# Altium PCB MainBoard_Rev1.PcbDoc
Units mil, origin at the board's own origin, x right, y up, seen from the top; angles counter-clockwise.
Board outline 3937.5 x 3937.01 mil, 4 copper layers (Layer 1, Layer 2, Layer 3, Layer 4), stack 68.734 mil thick; 72 components, 52 nets, 360 pads, 166 vias.
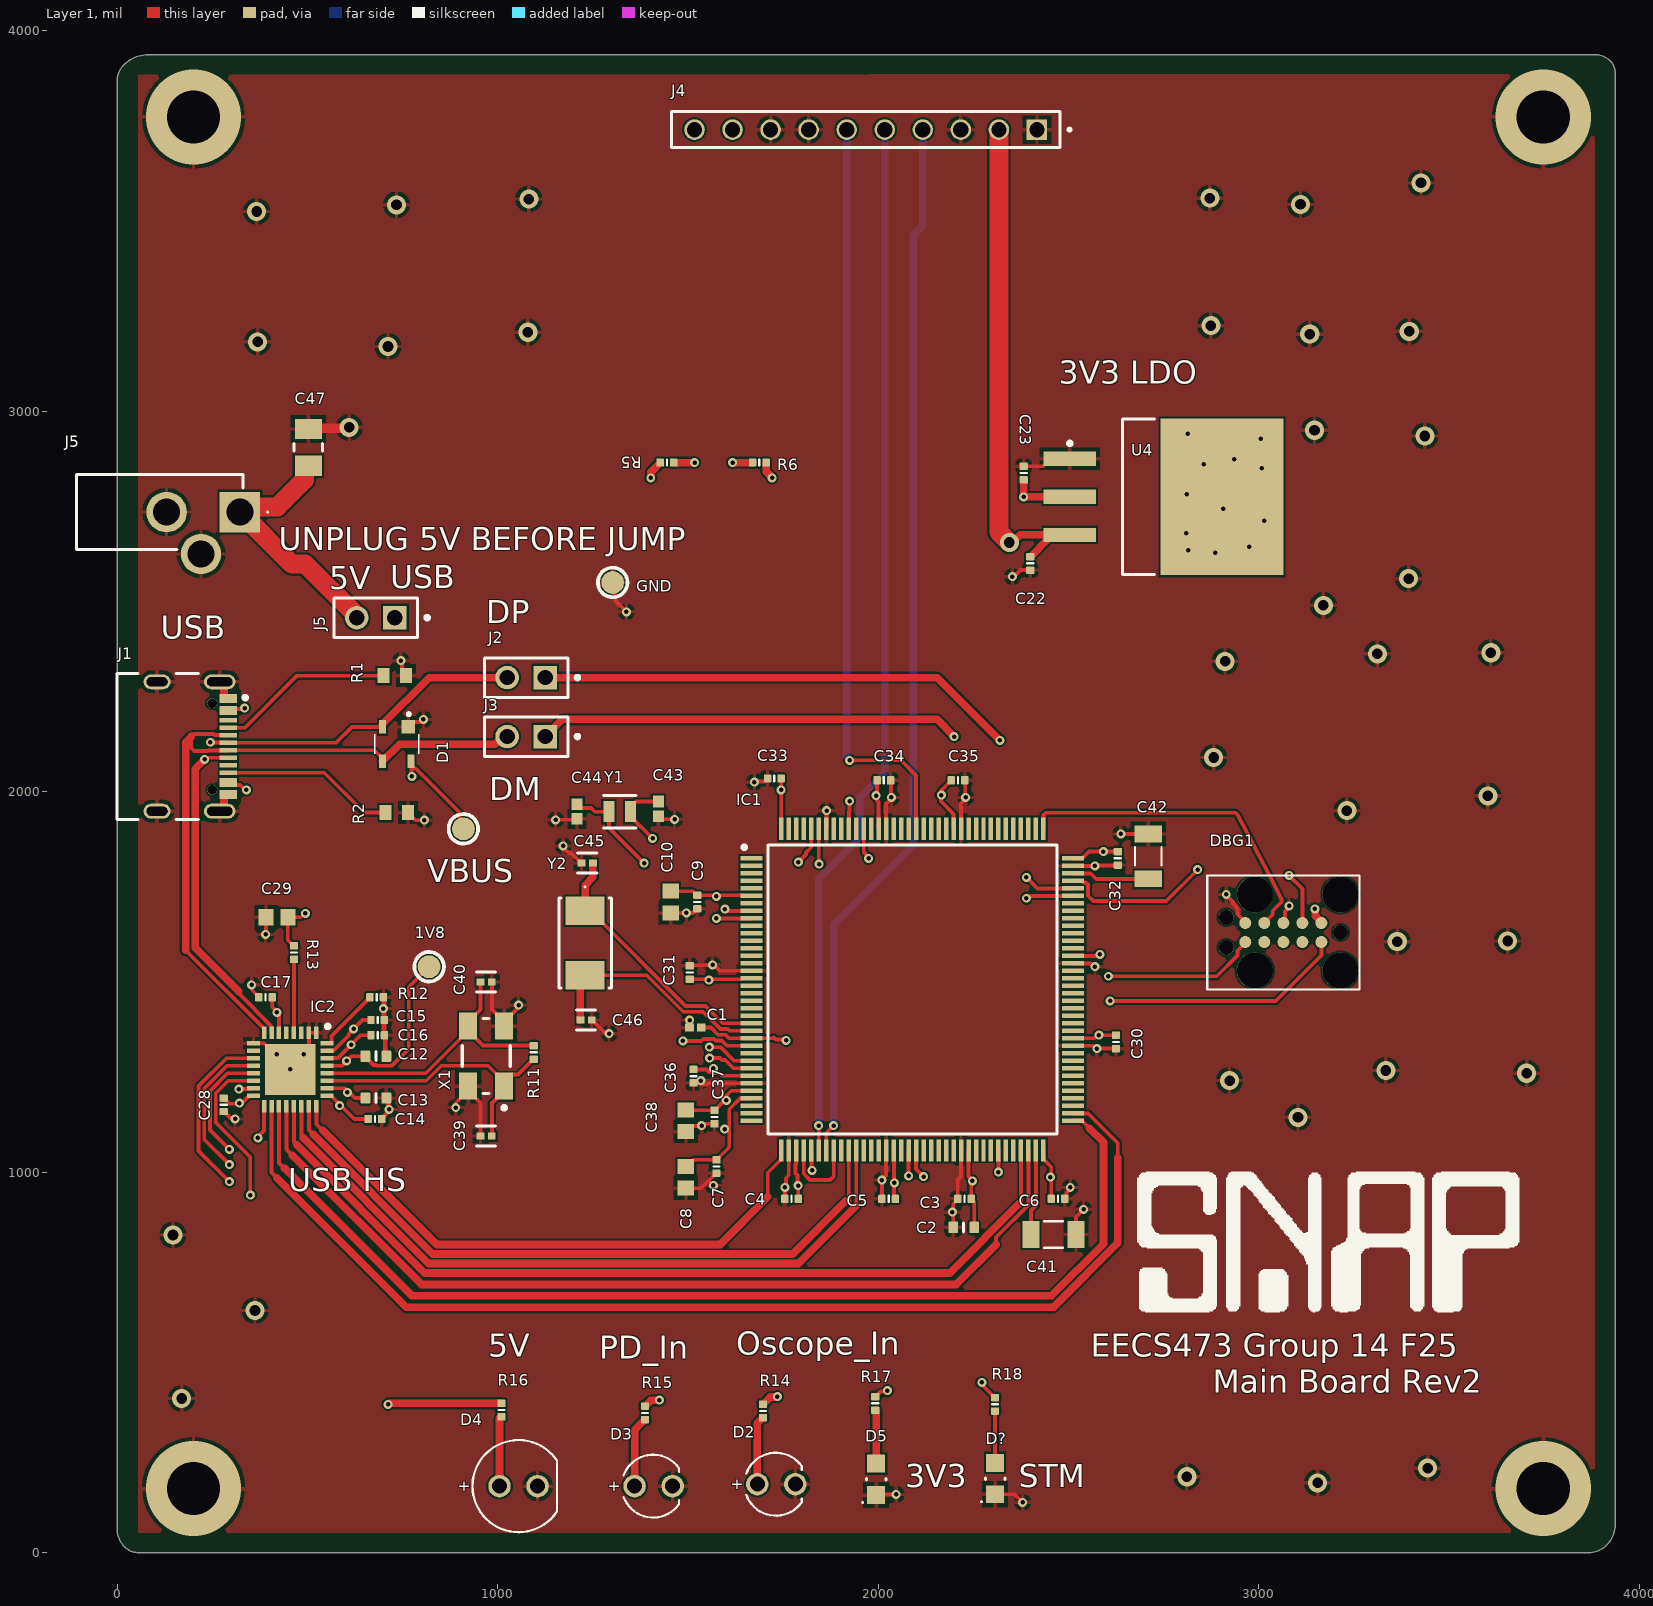
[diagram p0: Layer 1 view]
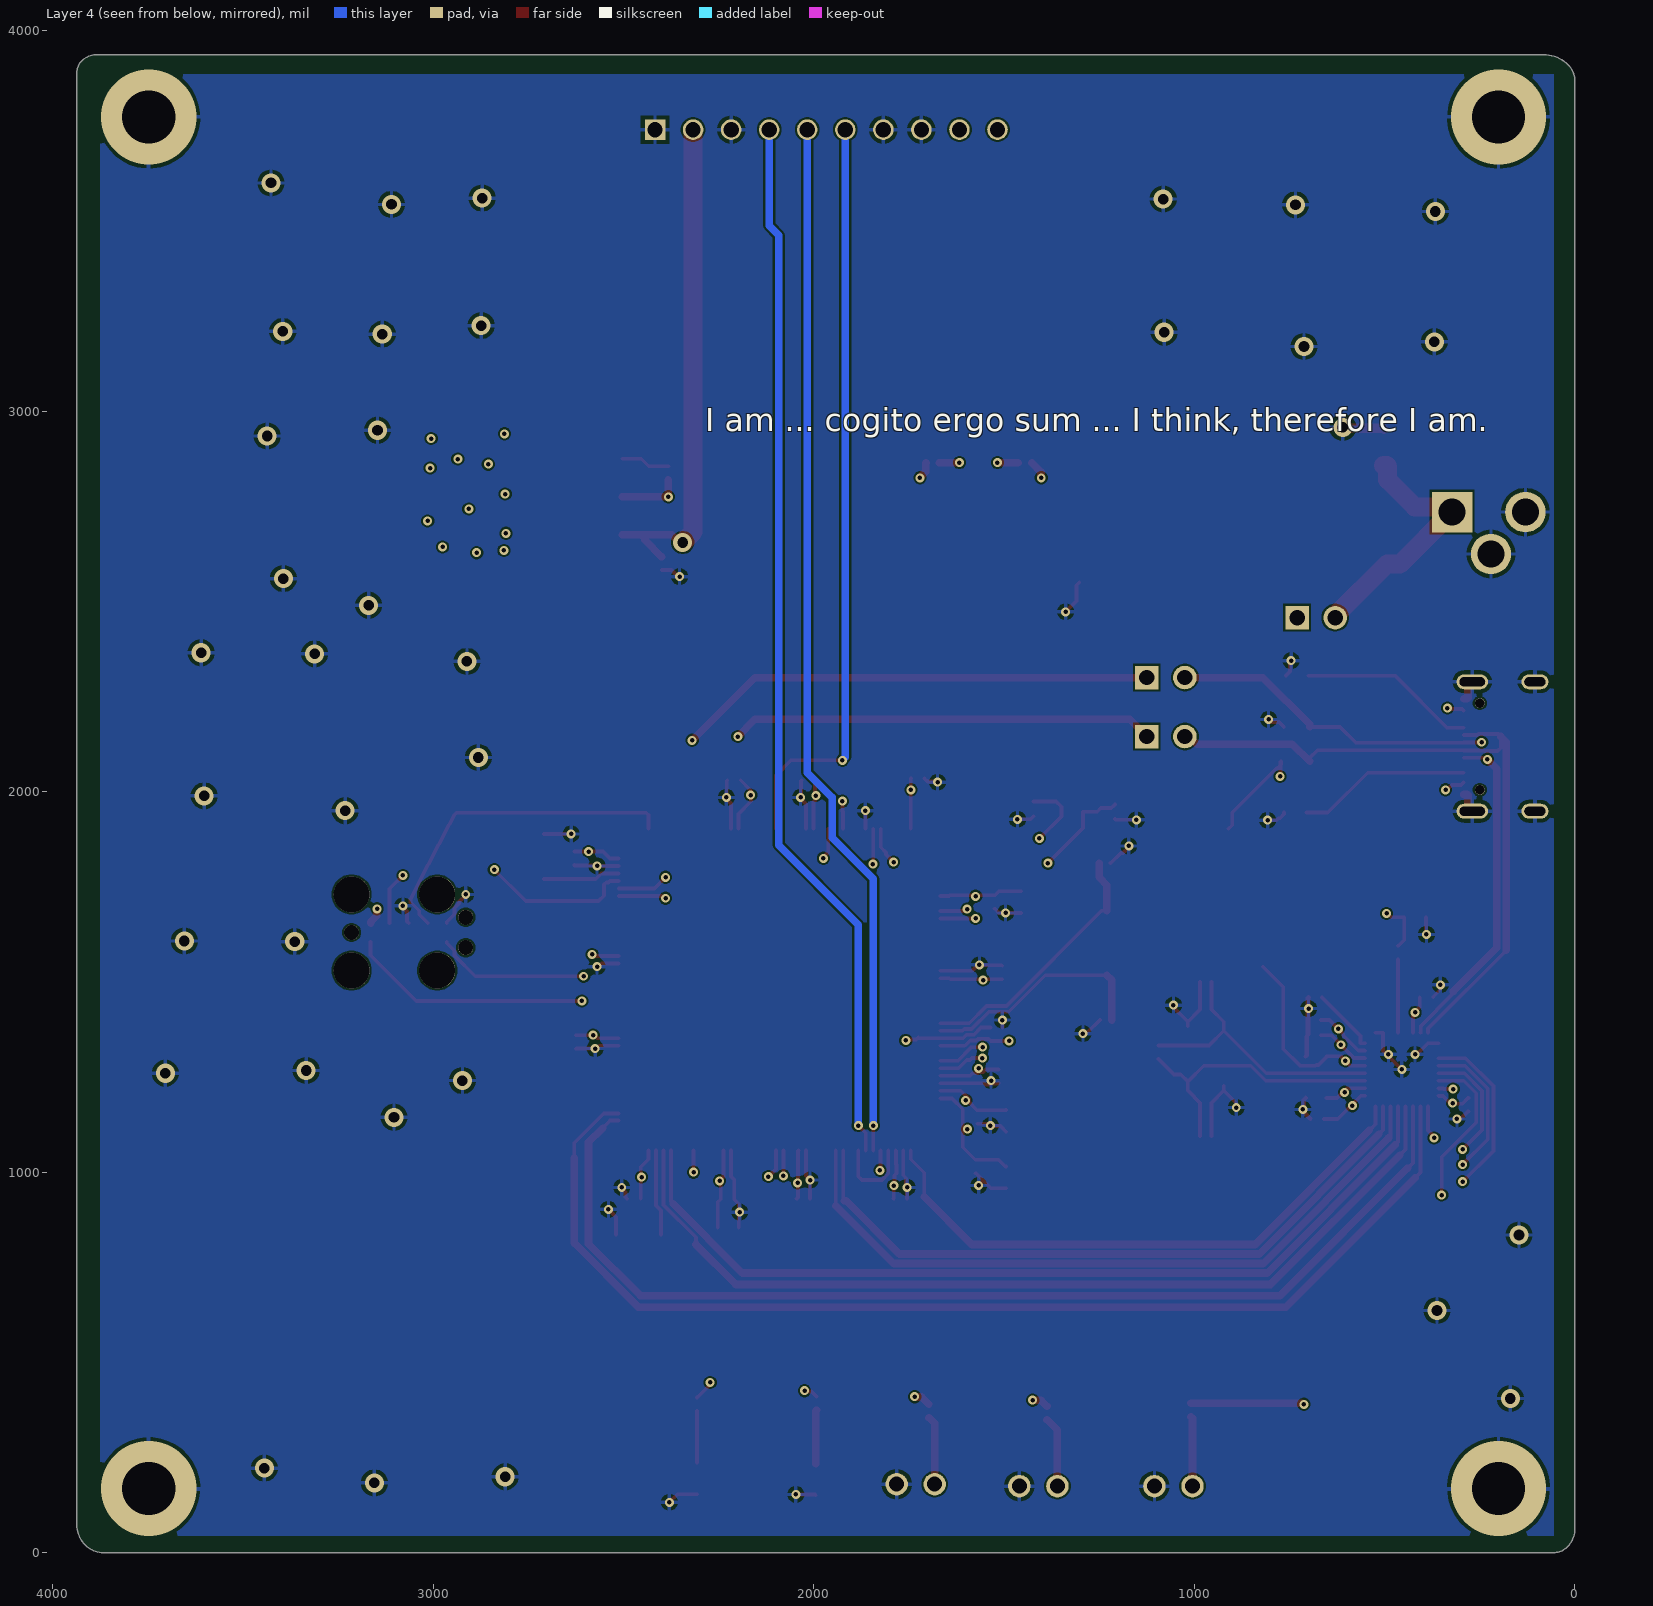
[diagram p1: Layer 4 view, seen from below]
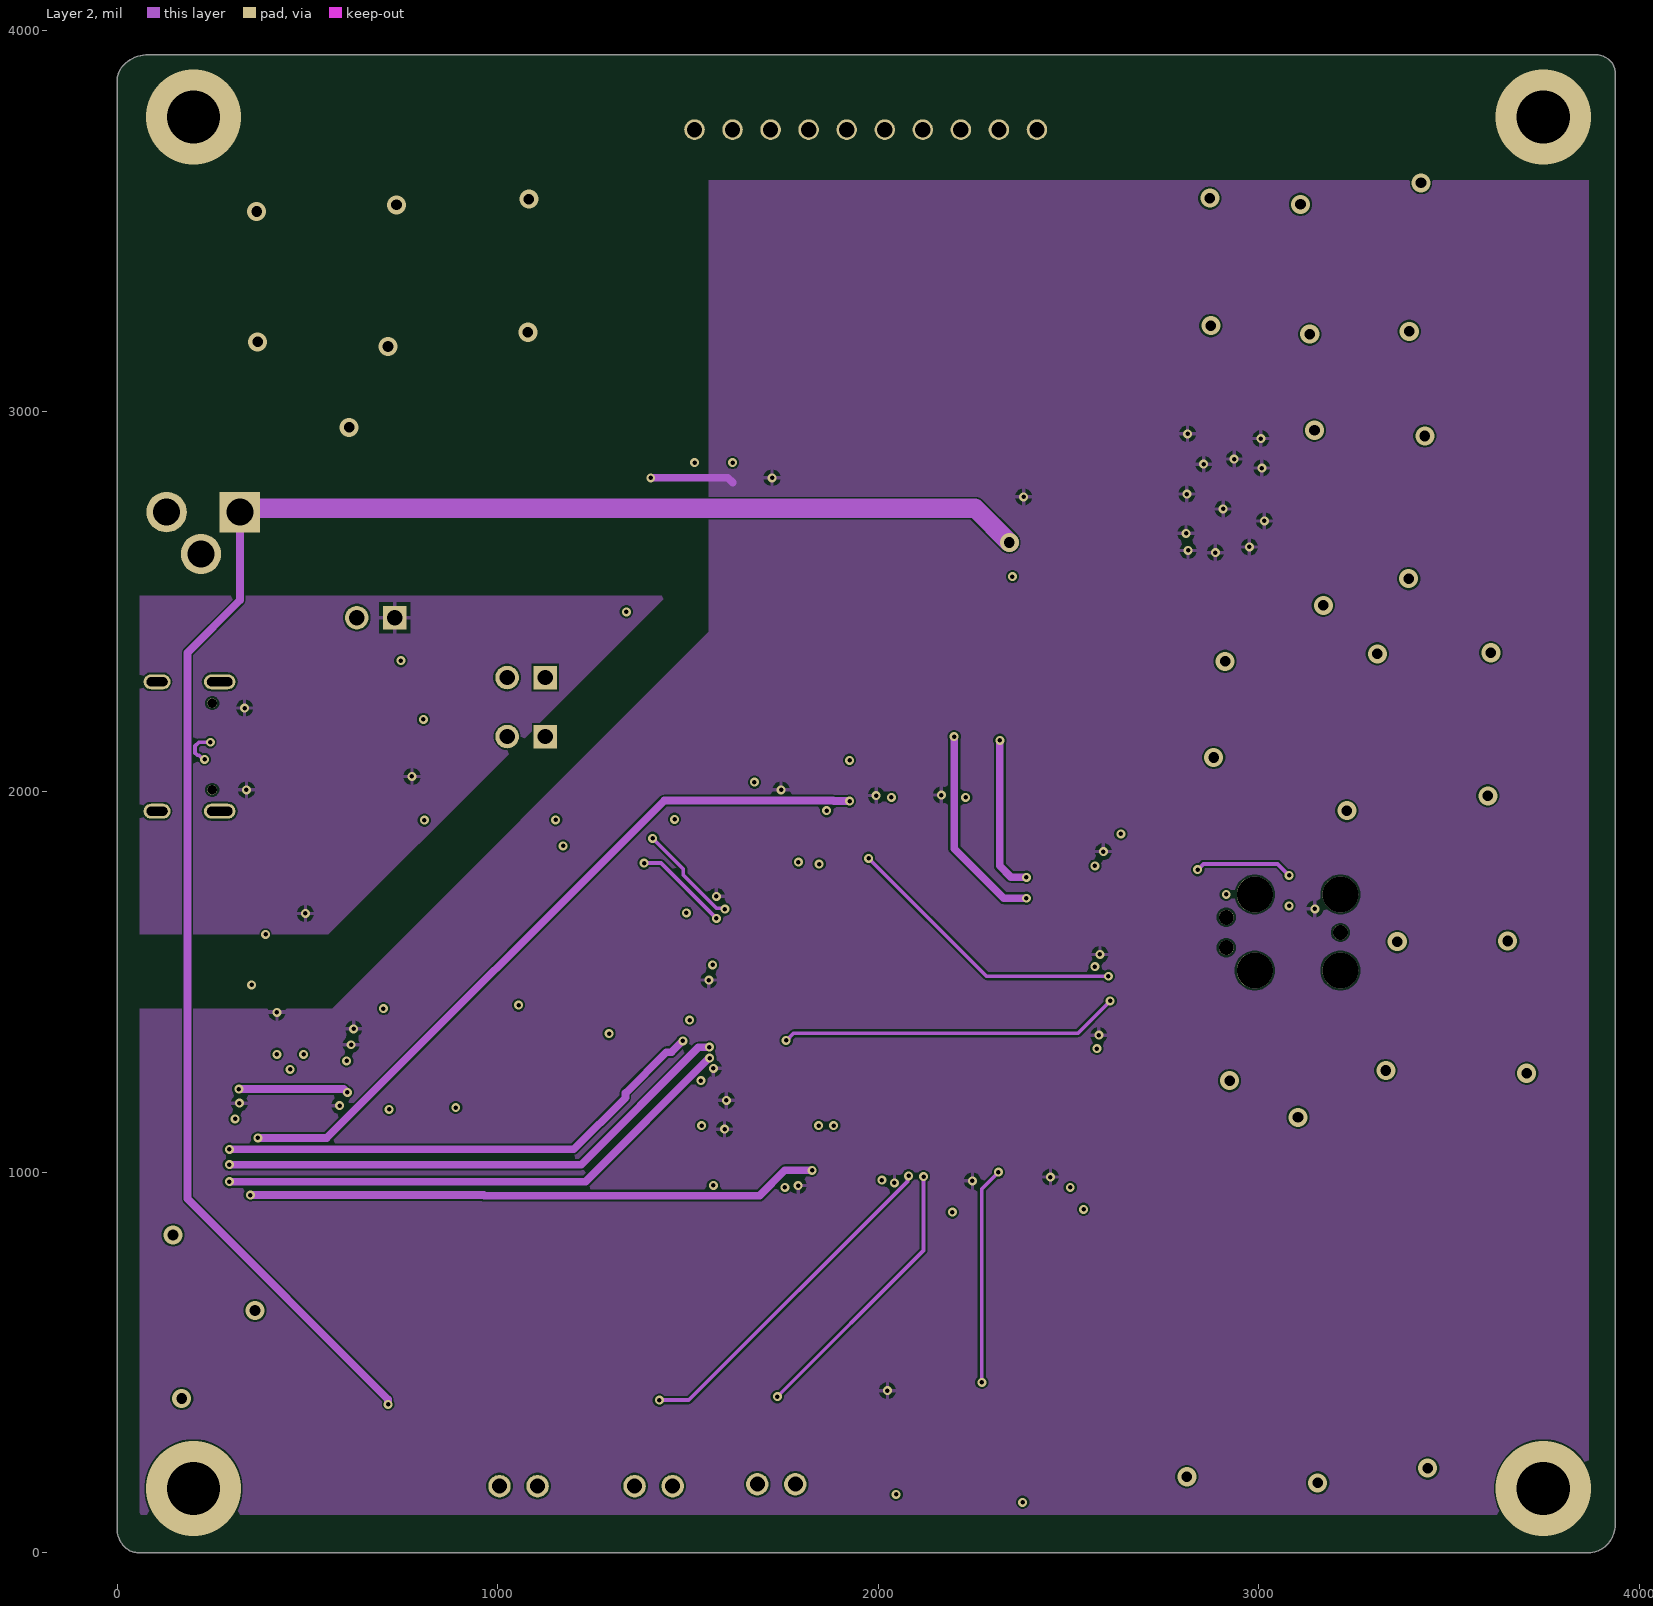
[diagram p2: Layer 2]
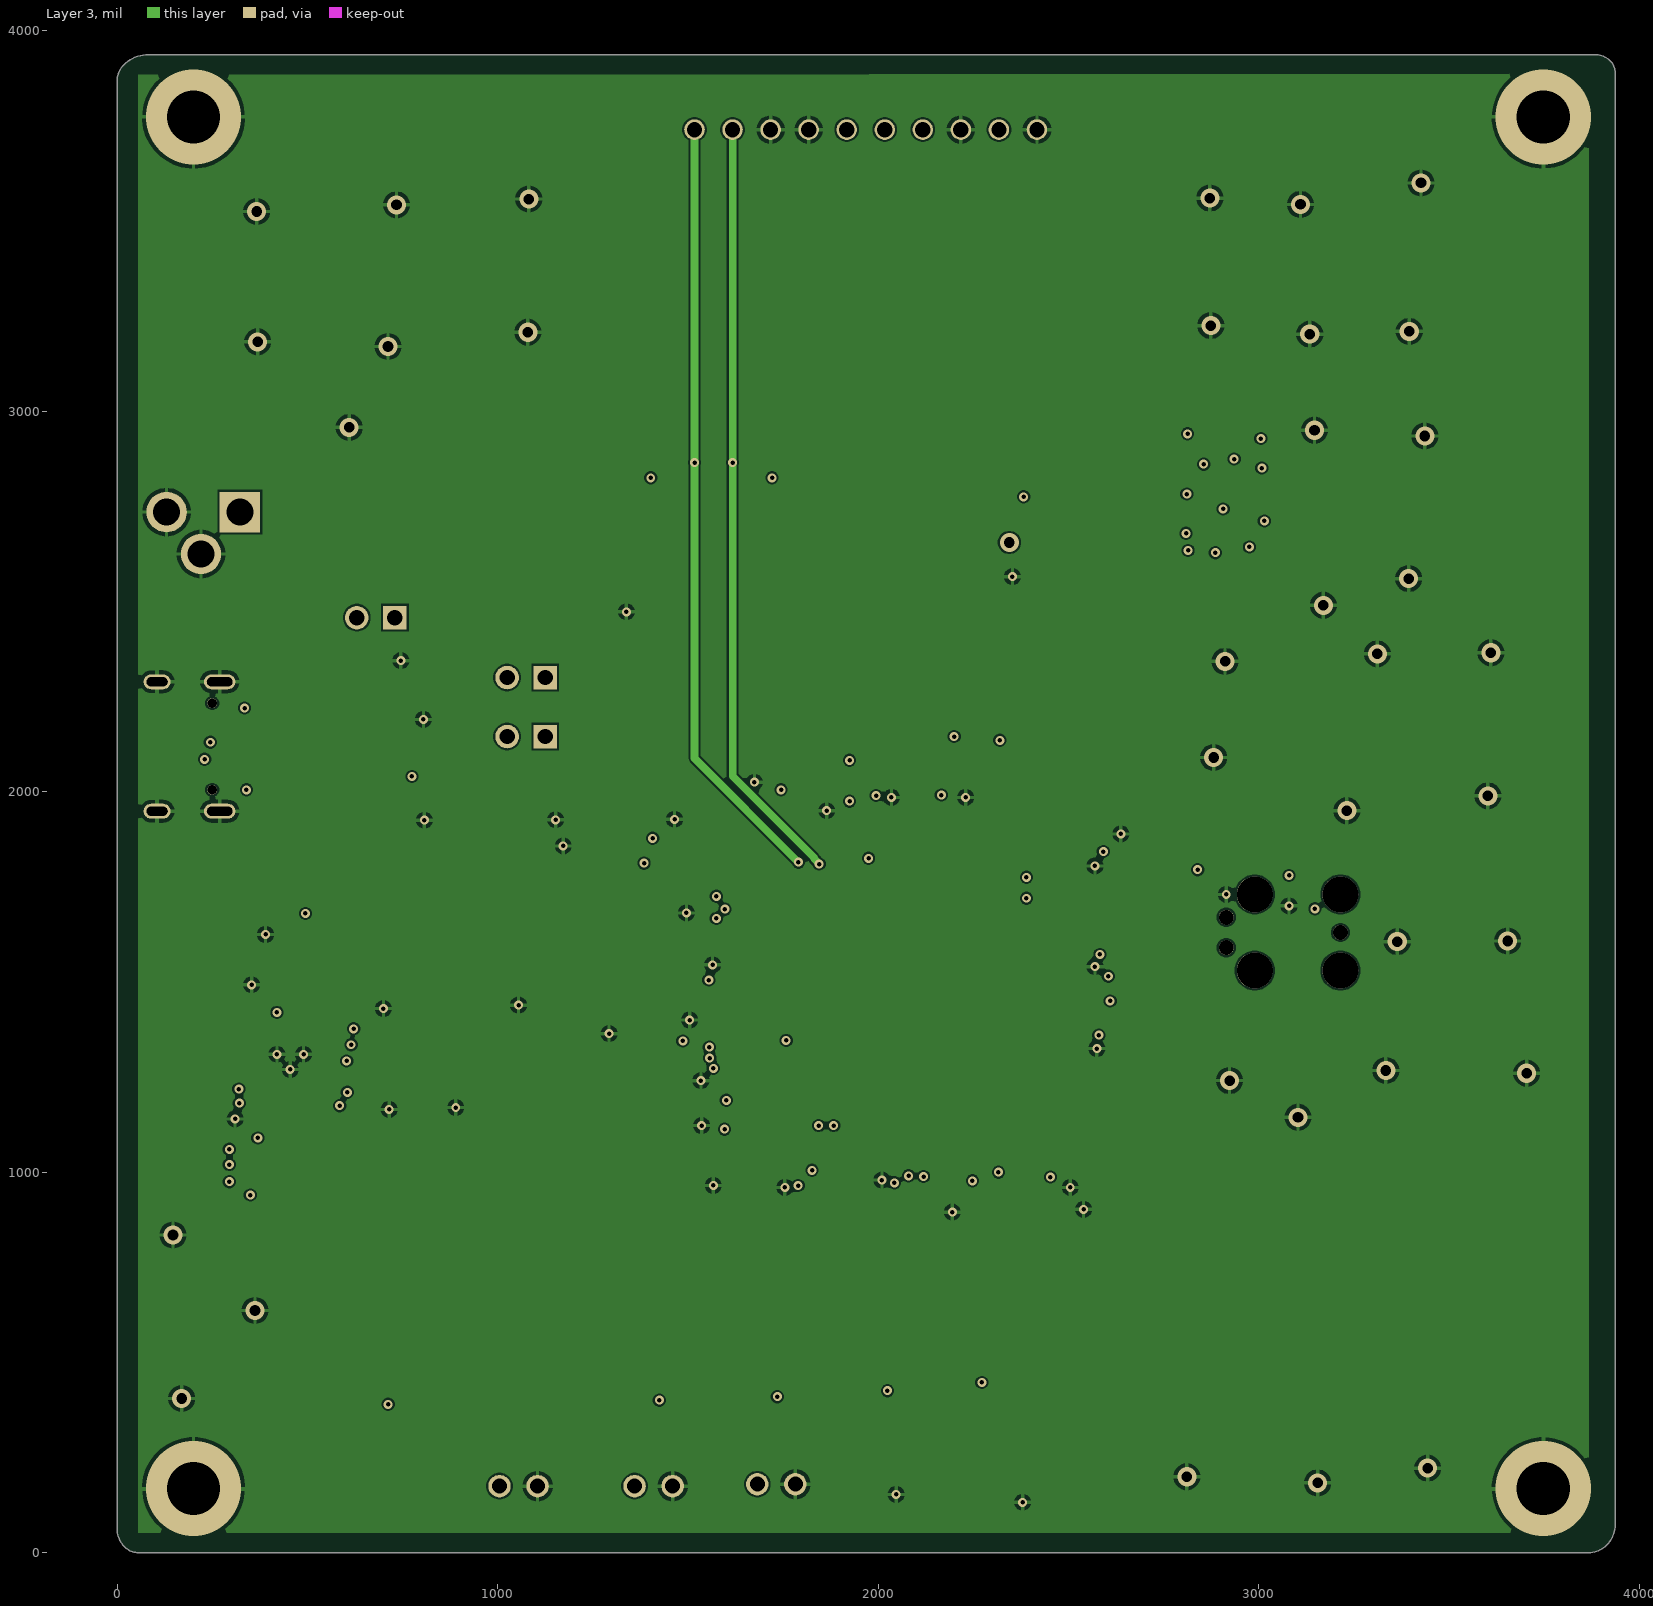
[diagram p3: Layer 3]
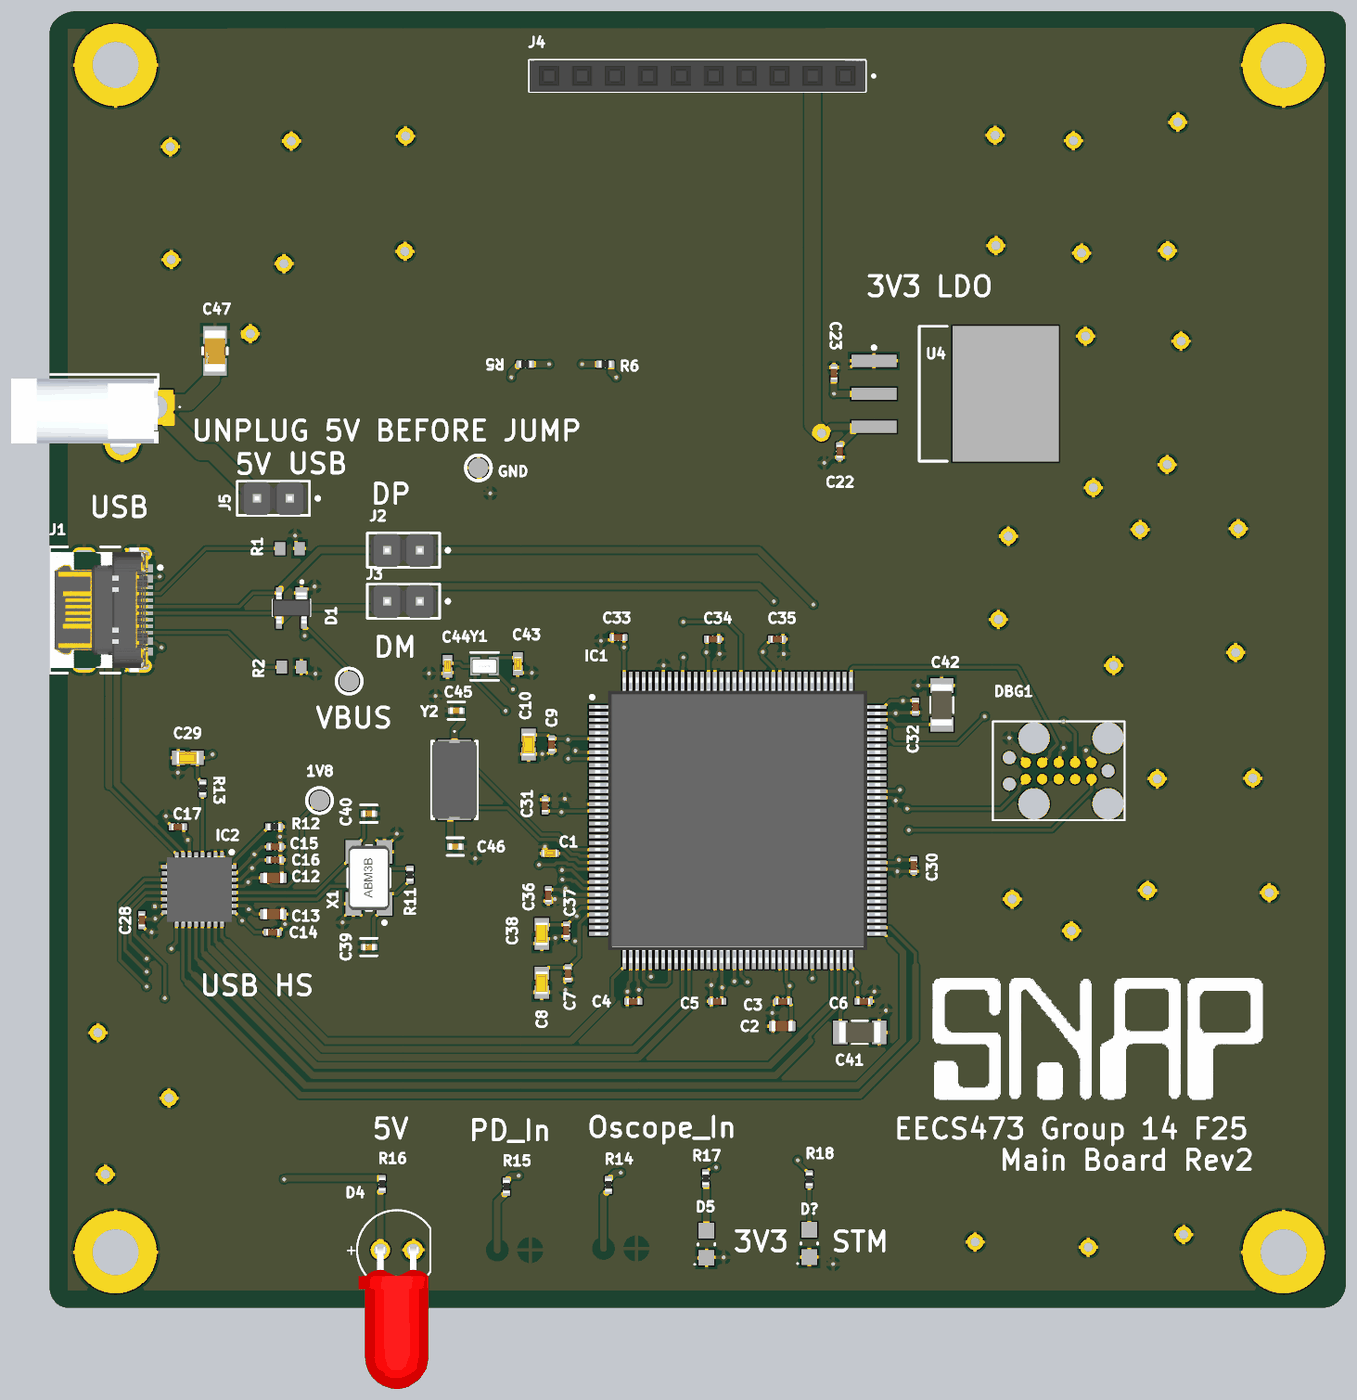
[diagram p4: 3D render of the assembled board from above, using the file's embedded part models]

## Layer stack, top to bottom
Top Solder: solder mask 0.4, Solder Resist, Dk 3.5
Layer 1: signal copper 1.378
Dielectric 2: prepreg 2.8, PP-006, Dk 4.1
Layer 2: signal copper 0.689
Dielectric 1: dielectric 59, FR-4, Dk 4.8
Layer 3: signal copper 0.689
Dielectric 3: prepreg 2.8, PP-006, Dk 4.1
Layer 4: signal copper 1.378
Bottom Solder: solder mask 0.4, Solder Resist, Dk 3.5

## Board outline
20,15 cw(c68.28,63.28) 0,63.28 0,3867.75 cw(c59.75,3867.75) 17.5,3910 cw(c82.7,3844.8) 82.7,3937.01 3883.94,3937.01 cw(c3883.94,3878.94) 3925,3920 cw(c3896.01,3891.01) 3937.01,3891.01 3937.01,81.19 ccw(c3938.69,81.19) 3937.5,80 3937.01,80 3937.01,73.13 cw(c3861.87,73.13) 3915,20 3914.45,19.45 cw(c3867.5,66.39) 3867.5,0 56.21,0 cw(c56.21,51.21)

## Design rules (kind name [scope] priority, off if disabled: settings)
Clearance [All] p1: gap=5 ignorepadtopadclearanceinfootprint=FALSE
PolygonConnect [All] p1: connectstyle=Relief reliefconductorwidth=10 reliefentries=4 polygonreliefangle="90 Angle" airgapwidth=10
RoutingVias [All] p1: holewidth=28 width=50 viastyle="Through Hole" minholewidth=28 minwidth=50 maxholewidth=28 maxwidth=50
SolderMaskExpansion [All] p1: expansion=4 istentingtop=FALSE
SupplyNets "Schematic Supply Nets_1" [InNet('GND')] p1: voltage=0.000
SupplyNets "Schematic Supply Nets_4" [InNet('3V3')] p2: voltage=0.000
SupplyNets "Schematic Supply Nets_3" [InNet('5V')] p3: voltage=0.000
Width [All] p1: maxlimit=50 minlimit=10 preferedwidth=10 minimp=50.000000 maximp=50.000000 favimp=50.000000
30 further rules are at their usual default settings.

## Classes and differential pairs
component class Designator: C1 C2 C3 C4 C5 C6 C7 C8 C9 C10 C30 C31 C32 C33 C34 C35 C36 C37 C38 C41 C42 C43 C44 C45 C46 D2 D3 D4 D5 D? DBG1 GND IC1 R14 R15 R16 R17 R18 Y1 Y2

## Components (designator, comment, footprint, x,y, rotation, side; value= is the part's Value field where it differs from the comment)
1V8 "TESTPAD" TESTPAD-Footprint-1 820,1540 r0 top
C1 "Capacitor 0.1 uF +/- 5% 16 V 0402" CAPC1005X56X25LL10T15 1519.65,1380 r0 top value=100nF
C2 "Capacitor 4.7µF +/-20% 10V 0603" CAPC0603(1608)100_L 2225,855 r0 top value=4.7µF
C3 "Capacitor 100nF +/-20% 10V 0402" CAPC0402(1005)60_L 2227.28,930 r0 top value=100nF
C4 "Capacitor 100nF +/-20% 10V 0402" CAPC0402(1005)60_L 1772.72,930 r0 top value=100nF
C5 "Capacitor 100nF +/-20% 10V 0402" CAPC0402(1005)60_L 2027.72,930 r0 top value=100nF
C6 "Capacitor 100nF +/-20% 10V 0402" CAPC0402(1005)60_L 2472.72,930 r180 top value=100nF
C7 "Capacitor 100nF +/-20% 10V 0402" CAPC0402(1005)60_L 1575,1015 r90 top value=100nF
C8 "Capacitor 1uF +/- 10% 16V 0603" CAPC1608X90X35ML15T15 1495,986.46 r90 top value=1µF
C9 "Capacitor 100nF +/-20% 10V 0402" CAPC0402(1005)60_L 1525,1710 r90 top value=100nF
C10 "Capacitor 1uF +/- 10% 16V 0603" CAPC1608X90X35ML15T15 1455,1710 r90 top value=1µF
C12 "Capacitor 4.7µF +/-20% 10V 0603" CAPC0603(1608)100_L 680,1305 r180 top value=4.7µF
C13 "Capacitor 4.7µF +/-20% 10V 0603" CAPC0603(1608)100_L 680,1195 r180 top value=4.7µF
C14 "Capacitor 100nF +/-20% 10V 0402" CAPC0402(1005)60_L 677.72,1140 r180 top value=100nF
C15 "Capacitor 100nF +/-20% 10V 0402" CAPC0402(1005)60_L 685,1400 r180 top value=100nF
C16 "Capacitor 100nF +/-20% 10V 0402" CAPC0402(1005)60_L 685,1360 r180 top value=100nF
C17 "Capacitor 100nF +/-20% 10V 0402" CAPC0402(1005)60_L 390,1460 r0 top value=100nF
C22 "Capacitor 10µF +/-40% 6.3V 0402" CAPC0402(1005)60_L 2400,2600.22 r90 top value=10µF
C23 "Capacitor 10µF +/-40% 6.3V 0402" CAPC0402(1005)60_L 2382.5,2837.5 r270 top value=10µF
C28 "Capacitor 100nF +/-20% 10V 0402" CAPC0402(1005)60_L 280,1177.28 r90 top value=100nF
C29 "Capacitor 1uF +/- 10% 16V 0603" CAPC1608X90X35ML15T15 420,1670 r0 top value=1µF
C30 "Capacitor 100nF +/-20% 10V 0402" CAPC0402(1005)60_L 2625,1342.28 r90 top value=100nF
C31 "Capacitor 100nF +/-20% 10V 0402" CAPC0402(1005)60_L 1505,1525 r270 top value=100nF
C32 "Capacitor 100nF +/-20% 10V 0402" CAPC0402(1005)60_L 2630,1825 r90 top value=100nF
C33 "Capacitor 100nF +/-20% 10V 0402" CAPC0402(1005)60_L 1727.28,2035 r0 top value=100nF
C34 "Capacitor 100nF +/-20% 10V 0402" CAPC0402(1005)60_L 2015,2030 r180 top value=100nF
C35 "Capacitor 100nF +/-20% 10V 0402" CAPC0402(1005)60_L 2210,2030 r180 top value=100nF
C36 "Capacitor 100nF +/-20% 10V 0402" CAPC0402(1005)60_L 1515,1252.28 r90 top value=100nF
C37 "Capacitor 100nF +/-20% 10V 0402" CAPC0402(1005)60_L 1570,1145 r90 top value=100nF
C38 "Capacitor 1uF +/- 10% 16V 0603" CAPC1608X90X35ML15T15 1495,1135 r90 top value=1µF
C39 "27pF" FP-GCM155-0_05-IPC_C 970,1095 r180 top
C40 "27pF" FP-GCM155-0_05-IPC_C 970,1500 r0 top
C41 "0.2uF" CAPC3216X94N 2460.95,836.3 r180 top
C42 "0.2uF" CAPC3216X94N 2710,1830 r270 top
C43 "Capacitor 0.5 pF +/- 0.1pF 25 V 0402" CAPC1005X56X25ML10T15 1422.5,1955 r90 top value=0.5pF
C44 "Capacitor 0.5 pF +/- 0.1pF 25 V 0402" CAPC1005X56X25ML10T15 1208.86,1947.89 r90 top value=0.5pF
C45 "3.9pF" FP-GJM155-0_05-IPC_C 1235.57,1812.5 r180 top
C46 "3.9pF" FP-GJM155-0_05-IPC_C 1232.5,1400 r0 top
C47 "220uF" FP-GRM31C-0_3-e0_3_0_9-IPC_C 502.5,2905 r270 top
D1 "TPD2E001DZDR" TPD2E001DZDR 735,2125 r180 top
D2 "151031VS06000" WL-TMRC_D3.95H5.3 51732.5,50180 r0 top
D3 "151031VS06000" WL-TMRC_D3.95H5.3 51410,50175 r0 top
D4 "151051RS11000" WL-TMRC_D5.9H8.7 1054.99,174.99 r0 top
D5 "LTST-C170KGKT" LTST-LTST-C170KGKT-2_V 1995,192.5 r90 top
D? "LTST-C170KGKT" LTST-LTST-C170KGKT-2_V 2307.5,195 r90 top
DBG1 "TC2050-IDC" TC2050-IDC-Footprint-1 3065,1630 r180 top
GND "TESTPAD" TESTPAD-Footprint-1 1302.5,2550 r0 top
IC1 "STM32H723ZGT6" QFP50P2200X2200X160-144N 2090,1480 r0 top
IC2 "USB3300-EZK" QFN50P500X500X100-33N-D 455,1270 r270 top
J1 "USB4105-GF-A" FP-USB4105-GF-A-MFG 150.98,2118.78 r270 top
J2 "M20-9990246" FP-M20-9990246-MFG 1075,2300 r180 top
J3 "M20-9990246" FP-M20-9990246-MFG 1075,2145 r180 top
J4 "SSQ-110-04-G-S" SAMTEC_SSQ-110-04-G-S 1967.5,3740 r180 top
J5 "M20-9990246" FP-M20-9990246-MFG 680,2457.5 r180 top
J5 "PJ-007" PJ007 322.91,2735 r0 top
R1 "5.1k" RESC1608X55X25ML10T15 730,2305 r0 top
R2 "5.1k" RESC1608X55X25ML10T15 735,1945 r0 top
R5 "Resistor 1K +/-5 % 0402 63 mW" RESC0402(1005)_L 1445,2865 r180 top value=1k
R6 "Resistor 1K +/-5 % 0402 63 mW" RESC0402(1005)_L 1687.72,2865 r0 top value=1k
R11 "Resistor 1M +/-1 % 0402 63 mW" RESC0402(1005)_L 1095,1315 r90 top value=1M
R12 "12KR2F" RESC0402(1005)_L 682.28,1460 r180 top value=12k
R13 "Resistor 10K  +/-1 % 0402 63 mW" RESC0402(1005)_L 465,1577.28 r270 top value=10k
R14 "100R2F" RESC0402(1005)_L 1697.5,372.5 r270 top value=100
R15 "100R2F" RESC0402(1005)_L 1387.5,367.5 r270 top value=100
R16 "200R2J" RESC0402(1005)_L 1010,375 r270 top value=200
R17 "100R2F" RESC0402(1005)_L 1992.5,392.5 r270 top value=100
R18 "100R2F" RESC0402(1005)_L 2307.5,390 r270 top value=100
U4 "LD1085D2M33R" D2PAK_A_L 2750,2775 r0 top
VBUS "TESTPAD" TESTPAD-Footprint-1 910,1902.5 r90 top
X1 "ABM3B-24.000MHZ-B2-T" ABRA-ABM3B-4_V 970,1305 r90 top
Y1 "ABS06-32.768KHZ-T" FP-ABS06-MFG 1321.04,1947.5 r180 top
Y2 "ABM7-25.000MHZ-4-T" ABM7 1230,1602.5 r270 top

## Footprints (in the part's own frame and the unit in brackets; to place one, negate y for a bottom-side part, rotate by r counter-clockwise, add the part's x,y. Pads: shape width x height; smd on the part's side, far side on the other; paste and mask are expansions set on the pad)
ABM7 [mm]
  rect 1.9x2.6 smd: 1(-2.15,0) 2(2.15,0)
  silkscreen extent -3.8,-1.75 3,1.75, body extent -3,-1.75 3,1.75, height 1.4
ABRA-ABM3B-4_V [mm] "SMD, 4-Leads, Body 5x3.2mm"
  rect 1.8x1.2 smd: 1(-2,-1.2) 2(2,-1.2) 3(2,1.2) 4(-2,1.2)
  silkscreen extent -3.57,-1.6 2.5,1.6, body extent -2.5,-1.59 2.5,1.59, height 1.13
CAPC0402(1005)60_L [mm] "Chip Capacitor, Body 1.0x0.5mm, Height 0.6mm, IPC High Density"
  rrect25% 0.5x0.55 smd: 1(-0.45,0) 2(0.45,0)
  silkscreen extent 0,-0.2 0,0.2, body extent -0.5,-0.25 0.5,0.25, height 0.6
CAPC0603(1608)100_L [mm] "Chip Capacitor, Body 1.6x0.8mm, Height 1.0mm, IPC High Density"
  rrect25% 0.66x0.76 smd: 1(-0.7,0) 2(0.7,0)
  silkscreen extent 0,-0.3 0,0.3, body extent -0.8,-0.4 0.8,0.4, height 0.95
CAPC1005X56X25LL10T15 [mm] "Chip Capacitor, 2-Leads, Body 1.10x0.60mm, IPC High Density"
  rect 0.58x0.54 smd: 1(-0.39,0) 2(0.39,0)
  body extent -0.55,-0.3 0.55,0.3, height 0.56
CAPC1005X56X25ML10T15 [mm] "Chip Capacitor, 2-Leads, Body 1.10x0.60mm, IPC Low Density"
  rect 0.78x0.74 smd: 1(-0.49,0) 2(0.49,0)
  body extent -0.55,-0.3 0.55,0.3, height 0.56
CAPC1608X90X35ML15T15 [mm] "Chip Capacitor, 2-Leads, Body 1.75x0.95mm, IPC Low Density"
  rect 1x1.1 smd: 1(-0.725,0) 2(0.725,0)
  body extent -0.87,-0.48 0.87,0.48, height 0.9
CAPC3216X94N [mil]
  rect 44x71 smd: 1(-59,0) 2(59,0)
  silkscreen extent -24,-35 24,35, body extent -63,-31 63,31, height 37
D2PAK_A_L [mm] "D2-PAK, 4-Leads, Body 9.2x10.2mm, Pitch 2.54mm, Lead Span 15.4mm, IPC High Density"
  rect 3.5x0.95 smd: 1(-6.25,2.54) 2(-6.25,0) 3(-6.25,-2.54)
  rect 8.2x10.45 smd: 4(3.9,0)
  silkscreen extent -6.37,-5.2 -0.6,5.2, body extent -2.75,-5.2 6.6,5.2, height 4.6
FP-ABS06-MFG [mm]
  rect 0.75x1.4 smd paste+0 mask+0: 1(-0.725,0) 2(0.725,0)
  silkscreen extent -1.07,-1.07 1.07,1.07, body extent -1.2,-0.8 1.2,0.8, height 0.25
FP-GCM155-0_05-IPC_C [mil]
  rect 20.29x18.6 smd paste+0 mask+0: 1(-14.9,0) 2(14.9,0)
  silkscreen extent -25,-27 25,27, body extent -29,-15 29,15, height 10
FP-GJM155-0_05-IPC_C [mil]
  rect 20.29x18.6 smd paste+0 mask+0: 1(-14.9,0) 2(14.9,0)
  silkscreen extent -25,-27 25,27, body extent -29,-15 29,15, height 10
FP-GRM31C-0_3-e0_3_0_9-IPC_C [mil]
  rect 53.28x71.03 smd paste+0 mask+0: 1(-48.25,0) 2(48.25,0)
  silkscreen extent -10,-37 10,37, body extent -79,-41 79,41, height 10
FP-M20-9990246-MFG [mm]
  rect 1.57x1.57 hole 1.02 paste-2539.97 mask+0: 1(-1.27,0)
  round 1.57 hole 1.02 paste-2539.97 mask+0: 2(1.27,0)
  silkscreen extent -3.55,-1.32 2.79,1.32, body extent -2.89,-1.42 2.89,1.42, height 0.25
FP-USB4105-GF-A-MFG [mm]
  rrect100% 1x2.1 hole 1.7 slot 0.6 at 0 deg paste-2539.97 mask+0: 1(-4.32,3.015) 2(4.32,3.015)
  rrect100% 1x1.8 hole 1.4 slot 0.6 at 0 deg paste-2539.97 mask+0: 3(-4.32,-1.165) 4(4.32,-1.165)
  rect 0.6x1.15 smd paste+0 mask+0: A1-B12(-3.2,3.59) A4-B9(-2.4,3.59) B1-A12(3.2,3.59) B4-A9(2.4,3.59)
  rect 0.3x1.15 smd paste+0 mask+0: A5(-1.25,3.59) A6(-0.25,3.59) A7(0.25,3.59) A8(1.25,3.59) B5(1.75,3.59) B6(0.75,3.59) B7(-0.75,3.59) B8(-1.75,3.59)
  round 0.65 hole 0.65 unplated paste-2539.97 mask+0: ""(-2.89,2.515) ""(2.89,2.515)
  silkscreen extent -4.86,-3.84 4.86,4.84, body extent -4.96,-3.94 4.96,4.27, height 0.25
LTST-LTST-C170KGKT-2_V [mm] "SMD, 2-Leads, Body 2.00x1.25mm"
  rect 1.2x1.2 smd: 1(-1.05,0) 2(1.05,0)
  silkscreen extent -1.6,-0.65 0.05,0.95, body extent -1,-0.63 1,0.63, height 1.1
PJ007 [mm]
  rect 2.7x2.7 hole 1.8: 1(0,0)
  round 2.7 hole 1.8: 2(-4.9,0) 3(-2.6,-2.8)
  silkscreen extent -10.9,-2.5 1.9,2.5, body extent -11.19,-3.17 0.26,2.18, height 7.41
QFN50P500X500X100-33N-D [mm]
  rect 0.85x0.3 smd: 1(-2.45,1.75) 2(-2.45,1.25) 3(-2.45,0.75) 4(-2.45,0.25) 5(-2.45,-0.25) 6(-2.45,-0.75) 7(-2.45,-1.25) 8(-2.45,-1.75) 17(2.45,-1.75) 18(2.45,-1.25) 19(2.45,-0.75) 20(2.45,-0.25) 21(2.45,0.25) 22(2.45,0.75) 23(2.45,1.25) 24(2.45,1.75)
  rect 0.3x0.85 smd: 9(-1.75,-2.45) 10(-1.25,-2.45) 11(-0.75,-2.45) 12(-0.25,-2.45) 13(0.25,-2.45) 14(0.75,-2.45) 15(1.25,-2.45) 16(1.75,-2.45) 25(1.75,2.45) 26(1.25,2.45) 27(0.75,2.45) 28(0.25,2.45) 29(-0.25,2.45) 30(-0.75,2.45) 31(-1.25,2.45) 32(-1.75,2.45)
  rect 3.4x3.4 smd: 33(0,0)
  silkscreen extent -3,2.38 -2.75,2.63, body extent -2.55,-2.55 2.55,2.55, height 1
QFP50P2200X2200X160-144N [mm]
  rect 1.475x0.3 smd: 1(-10.738,8.75) 2(-10.738,8.25) 3(-10.738,7.75) 4(-10.738,7.25) 5(-10.738,6.75) 6(-10.738,6.25) 7(-10.738,5.75) 8(-10.738,5.25) 9(-10.738,4.75) 10(-10.738,4.25) 11(-10.738,3.75) 12(-10.738,3.25) 13(-10.738,2.75) 14(-10.738,2.25) 15(-10.738,1.75) 16(-10.738,1.25) 17(-10.738,0.75) 18(-10.738,0.25) 19(-10.738,-0.25) 20(-10.738,-0.75) 21(-10.738,-1.25) 22(-10.738,-1.75) 23(-10.738,-2.25) 24(-10.738,-2.75) 25(-10.738,-3.25) 26(-10.738,-3.75) 27(-10.738,-4.25) 28(-10.738,-4.75) 29(-10.738,-5.25) 30(-10.738,-5.75) 31(-10.738,-6.25) 32(-10.738,-6.75) 33(-10.738,-7.25) 34(-10.738,-7.75) 35(-10.738,-8.25) 36(-10.738,-8.75) 73(10.738,-8.75) 74(10.738,-8.25) 75(10.738,-7.75) 76(10.738,-7.25) 77(10.738,-6.75) 78(10.738,-6.25) 79(10.738,-5.75) 80(10.738,-5.25) 81(10.738,-4.75) 82(10.738,-4.25) 83(10.738,-3.75) 84(10.738,-3.25) 85(10.738,-2.75) 86(10.738,-2.25) 87(10.738,-1.75) 88(10.738,-1.25) 89(10.738,-0.75) 90(10.738,-0.25) 91(10.738,0.25) 92(10.738,0.75) 93(10.738,1.25) 94(10.738,1.75) 95(10.738,2.25) 96(10.738,2.75) 97(10.738,3.25) 98(10.738,3.75) 99(10.738,4.25) 100(10.738,4.75) 101(10.738,5.25) 102(10.738,5.75) 103(10.738,6.25) 104(10.738,6.75) 105(10.738,7.25) 106(10.738,7.75) 107(10.738,8.25) 108(10.738,8.75)
  rect 0.3x1.475 smd: 37(-8.75,-10.738) 38(-8.25,-10.738) 39(-7.75,-10.738) 40(-7.25,-10.738) 41(-6.75,-10.738) 42(-6.25,-10.738) 43(-5.75,-10.738) 44(-5.25,-10.738) 45(-4.75,-10.738) 46(-4.25,-10.738) 47(-3.75,-10.738) 48(-3.25,-10.738) 49(-2.75,-10.738) 50(-2.25,-10.738) 51(-1.75,-10.738) 52(-1.25,-10.738) 53(-0.75,-10.738) 54(-0.25,-10.738) 55(0.25,-10.738) 56(0.75,-10.738) 57(1.25,-10.738) 58(1.75,-10.738) 59(2.25,-10.738) 60(2.75,-10.738) 61(3.25,-10.738) 62(3.75,-10.738) 63(4.25,-10.738) 64(4.75,-10.738) 65(5.25,-10.738) 66(5.75,-10.738) 67(6.25,-10.738) 68(6.75,-10.738) 69(7.25,-10.738) 70(7.75,-10.738) 71(8.25,-10.738) 72(8.75,-10.738) 109(8.75,10.738) 110(8.25,10.738) 111(7.75,10.738) 112(7.25,10.738) 113(6.75,10.738) 114(6.25,10.738) 115(5.75,10.738) 116(5.25,10.738) 117(4.75,10.738) 118(4.25,10.738) 119(3.75,10.738) 120(3.25,10.738) 121(2.75,10.738) 122(2.25,10.738) 123(1.75,10.738) 124(1.25,10.738) 125(0.75,10.738) 126(0.25,10.738) 127(-0.25,10.738) 128(-0.75,10.738) 129(-1.25,10.738) 130(-1.75,10.738) 131(-2.25,10.738) 132(-2.75,10.738) 133(-3.25,10.738) 134(-3.75,10.738) 135(-4.25,10.738) 136(-4.75,10.738) 137(-5.25,10.738) 138(-5.75,10.738) 139(-6.25,10.738) 140(-6.75,10.738) 141(-7.25,10.738) 142(-7.75,10.738) 143(-8.25,10.738) 144(-8.75,10.738)
  silkscreen extent -11.35,-9.65 9.65,9.65, body extent -11,-11 11,11, height 1.6
RESC0402(1005)_L [mm] "Chip Resistor, Body 1.0x0.5mm, IPC High Density"
  rrect25% 0.5x0.55 smd: 1(-0.45,0) 2(0.45,0)
  silkscreen extent 0,-0.2 0,0.2, body extent -0.5,-0.25 0.5,0.25, height 0.3
RESC1608X55X25ML10T15 [mm] "Chip Resistor, 2-Leads, Body 1.60x0.80mm, IPC Low Density"
  rect 0.8x1 smd: 1(-0.75,0) 2(0.75,0)
  body extent -0.85,-0.45 0.85,0.45, height 0.55
SAMTEC_SSQ-110-04-G-S [mm]
  rect 1.37x1.37 / inner round 1.37 / far side rect 1.37x1.37 hole 1.02: 01(-11.43,0)
  round 1.37 hole 1.02: 02(-8.89,0) 03(-6.35,0) 04(-3.81,0) 05(-1.27,0) 06(1.27,0) 07(3.81,0) 08(6.35,0) 09(8.89,0) 10(11.43,0)
  silkscreen extent -13.7,-1.2 12.96,1.2, body extent -12.95,-1.21 12.95,1.21, height 8.51
TC2050-IDC-Footprint-1 [mm]
  round 0.8 smd paste-0.9: 1(-2.54,-0.635) 2(-1.27,-0.635) 3(0,-0.635) 4(1.27,-0.635) 5(2.54,-0.635) 6(2.54,0.635) 7(1.27,0.635) 8(0,0.635) 9(-1.27,0.635) 10(-2.54,0.635)
  round 1 hole 1 paste-2539.97: A(-3.81,0) B(3.81,-1.016) C(3.81,1.016)
  round 2.4 hole 2.4 paste-2539.97: D(-3.81,-2.54) E(1.905,-2.54) F(1.905,2.54) G(-3.81,2.54)
  silkscreen extent -5.08,-3.81 5.08,3.81
TESTPAD-Footprint-1 [mil]
  round 60 smd: PAD(0,0)
  silkscreen extent -39,-39 39,39
TPD2E001DZDR [mm]
  rect 0.91x0.91 smd: 1(-0.76,-1.15)
  rect 0.46x0.91 smd: 2(0.96,-1.15) 3(0.96,1.15) 4(-0.96,1.15)
  silkscreen extent -1.46,-2.1 1.46,0.65, body extent -1.46,-1.18 1.46,1.18, height 1.22
WL-TMRC_D3.95H5.3 [mm] "THT Mono-color Round Color LED, 2-leads"
  round 1.5 hole 1: 1(-1271.27,-1270) 2(-1268.73,-1270)
  silkscreen extent -1272,-1272.1 -1268.31,-1267.9, body extent -1271.99,-1271.97 -1268.37,-1268.03, height 5.35
WL-TMRC_D5.9H8.7 [mm] "THT Mono-color Round Color LED, 2-leads"
  round 1.5 hole 1: 1(-1.27,0) 2(1.27,0)
  silkscreen extent -3.07,-3.07 2.58,3.08, body extent -2.95,-10.7 2.45,0.25, height 5.95

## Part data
1V8 GND VBUS: library part CMP-002-00073-1, "PCB TESTPAD"
C1: library part CMP-001-00001-6, "Chip Capacitor, 0.1 uF, +/- 5%, 16 V, 0402 (1005 Metric)", Capacitor Type=Ceramic, Case/Package=0402, Max Operating Temperature=125°C, Min Operating Temperature=-55°C, Tolerance=5%, Voltage Rating=16V
C2 C12 C13: library part CMP-001-00076-4, "Chip Capacitor, 4.7µF +/-20%, 10V, 0603, Thickness 1 mm", Case/Package=0603, Max Operating Temperature=85°C, Min Operating Temperature=-55°C, Tolerance=10%, Voltage Rating=10V
C3 C4 C5 C6 C7 C9 C14 C15 C16 C17 C28 C30 C31 C32 C33 C34 C35 C36 C37: library part CMP-001-00061-3, "Chip Capacitor, 100nF +/-20%, 10V, 0402, Thickness 0.6 mm", Case/Package=0402, Max Operating Temperature=85°C, Min Operating Temperature=-55°C, Tolerance=20%, Voltage Rating=10V
C8 C10 C29 C38: library part CMP-001-00004-6, "Chip Capacitor, 1 uF, +/- 10%, 16 V, 0603 (1608 Metric)", Capacitor Type=Ceramic, Case/Package=0603, Max Operating Temperature=125°C, Min Operating Temperature=-55°C, Tolerance=10%, Voltage Rating=16V
C22 C23: library part CMP-001-00074-3, "Chip Capacitor, 10µF +/-40%, 6.3V, 0402, Thickness 0.6 mm", Case/Package=0402, Max Operating Temperature=85°C, Min Operating Temperature=-55°C, Tolerance=10%, Voltage Rating=6.3V
C39 C40: library part CMP-06035-034210-1, "Ceramic Capacitor for Automotive 27pF ±5% 50VDC C0G 0402 Paper T/R", Case/Package=0402, Max Operating Temperature=125°C, Min Operating Temperature=-55°C, Ratings=AEC-Q200, Tolerance=5%, Voltage Rating=50V
C41 C42: library part 12063C204KAT4A, "Capacitor", Manufacturer_Name="Kyocera AVX", Mouser Part Number=581-12063C204KAT4A
C43 C44: library part CMP-001-00002-6, "Chip Capacitor, 0.5 pF, +/- 0.1pF, 25 V, 0402 (1005 Metric)", Capacitor Type=Ceramic, Case/Package=0402, Max Operating Temperature=125°C, Min Operating Temperature=-55°C, Tolerance=20%, Voltage Rating=25V
C45 C46: library part CMP-2008-03853-2, "Multi-Layer Ceramic Capacitor 3.9pF C0G  ±0.25pF 0402 Paper T/R", Case Code (Imperial)=0402, Case Code (Metric)=1005, Dielectric=C0G, Max Operating Temperature=125°C, Min Operating Temperature=-55°C, Package Quantity=1, Voltage=50V
C47: library part CMP-06035-000079-2, "Chip Multilayer Ceramic Capacitors for General Purpose, 1206, 220uF, X5R, 15%, 20%, 6.3V", Case Code (Imperial)=1206, Case Code (Metric)=3216, Dielectric=X5R, Max Operating Temperature=85°C, Min Operating Temperature=-55°C, Tolerance=20%, Voltage Rating=6.3V
D1: "Diode", Manufacturer_Name="Texas Instruments", Mouser Part Number=595-TPD2E001DZDR
D2 D3: library part CMP-1488-00004-2, Case/Package=Radial, Color=Green, Forward Current=100mA, Forward Voltage=2.2V, Max Operating Temperature=85°C, Max Reverse Voltage (DC)=5V, Min Operating Temperature=-40°C, Test Current=20mA
D4: library part CMP-007-00039-1, "WL-TMRC Red Color Diffused 5 mm Round Through Hole LED", Case/Package=Radial, Forward Current=100mA, Forward Voltage=2.1V, Max Operating Temperature=85°C, Min Operating Temperature=-40°C
D5 D?: library part CMP-2000-06620-1, "Ultra Bright AlInGaP Chip LED, 75 mW, -55 to 85 degC, 2-Pin SMD (0805), RoHS, Tape and Reel", Emitting Color=YellowGreen, Forward Current=30mA, Forward Voltage=2.4V, Manufacturer=Lite-On, Operating Temp Range=-55Cto85C, Operating Temperature Classification=Industrial, Package Description="2-Pin Surface Mounted Device, Body 2 x 1.25 mm", Package Reference=LTST-C170KGKT-2, Package Type=ChipLed, Power Dissipation=75W, Power Dissipation Max=75mW, Reverse Voltage=5V, Test Current (It)=20mA
DBG1: library part CMP-002-00071-4, "CBL PLUG-OF-NAILS 10-PIN W/LEGS"
IC1: "Integrated Circuit", Manufacturer_Name=STMicroelectronics, Mouser Part Number=511-STM32H723ZGT6
IC2: "Integrated Circuit", Manufacturer_Name=Microchip, Mouser Part Number=886-USB3300-EZK
J1: library part CMP-002-00080-1, "Conn USB 2.0 Type C RCP 24 POS 0.3mm/0.5mm Solder RA SMD 24 Terminal 1 Port T/R"
J2 J3 J5: library part CMP-15831-000009-1, "CONN HEADER VERT 2POS 2.54MM", Current Rating=3A, Manufacturer=Harwin, Temperature="-40°C to +105°C", Temperature Range High=+105°C, Temperature Range Low=-40°C
J4: library part CMP-039-000000-3, "Samtec Connector .1\" pitch, long ahh pins", Package=None
J5: "Connector", Manufacturer_Name="Same Sky", Mouser Part Number=490-PJ-007
R1 R2: library part CMP-2000-04091-1, Manufacturer=Yageo, Part Number=RC0603FR-075K1L
R5 R6: library part CMP-009-00157-3, "Chip Resistor, 1 kOhms, +/-5 %, 63 mW, -55 to 155 degC, 0402", Case/Package=0402, Max Operating Temperature=155°C, Min Operating Temperature=-55°C, Power=63mW, Tolerance=5%
R11: library part CMP-009-00165-3, "Chip Resistor, 1 MOhms, +/-1 %, 63 mW, -55 to 155 degC, 0402", Case/Package=0402, Power=63mW, Tolerance=1%
R12: library part CMP-009-00071-2, "12K 0.063W 1% 0402 (1005 Metric)  SMD", Case/Package=0402, Power=63mW, Tolerance=1%
R13: library part CMP-009-00149-3, "Chip Resistor, 10 kOhms, +/-1 %, 63 mW, -55 to 125 degC, 0402", Case/Package=0402, Max Operating Temperature=155°C, Min Operating Temperature=-55°C, Power=63mW, Tolerance=1%
R14 R15 R17 R18: library part CMP-009-00065-2, "100R 0.063W 1% 0402 (1005 Metric)  SMD", Case/Package=0402, Power=63mW, Tolerance=1%
R16: library part CMP-009-00079-2, "200R 0.063W 5% 0402 (1005 Metric)  SMD", Case/Package=0402, Power=63mW, Tolerance=5%
U4: library part CMP-0244-00506-1, "3A, Low Drop Positive Voltage Regulator, 3.3V, 4-Pin D2PAK/A"
X1: library part CMP-003-00019-2, "Ceramic SMD Crystal, 24 MHz, +/- 20 ppm, 18 pF, -20 to 70 degC, 4-Pin SMD, RoHS, Tape and Reel", Case/Package=CSMD, Frequency=24MHz, Frequency Tolerance=20ppm, Load Capacitance=18pF, Manufacturer=Abracon, Max Operating Temperature=70°C, Min Operating Temperature=-20°C, Package Description="4-Pin Surface Mount Device, Body 5 x 3.2 mm", Package Quantity=1000, Package Reference=ABM3B, Resistance=50Ohm
Y1: library part CMP-2000-05035-2, "Crystal 32.768kHz ±20ppm (Tol) 12.5pF FUND 90kΩ 2-Pin Mini-CSMD T/R", Case/Package=CSMD, ESR (Equivalent Series Resistance)=90kR, Frequency=32.768kHz, Frequency Stability=20ppm, Insulation Resistance=500MR, Load Capacitance=12.5pF, Max Operating Temperature=85°C, Min Operating Temperature=-40°C, Operating Frequency="32.768 kHz", Package Quantity=3000
Y2: "Crystal or Oscillator", Manufacturer_Name=ABRACON, Mouser Part Number=815-ABM725000MHZ4T

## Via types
v1: diameter 23.62, hole 11.81, Layer 1 to Layer 4, tented top, 126 vias
v2: diameter 50, hole 28, Layer 1 to Layer 4, 36 vias
v3: diameter 250, hole 140, Layer 1 to Layer 4, 4 vias

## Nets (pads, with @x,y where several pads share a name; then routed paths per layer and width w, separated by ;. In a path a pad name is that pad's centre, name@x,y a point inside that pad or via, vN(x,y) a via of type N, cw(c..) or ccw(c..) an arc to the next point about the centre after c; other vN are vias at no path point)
3V3: C2.2 C3.2 C4.2 C5.2 C6.2 C7.2 C8.2 C9.2 C10.2 C14.2 C15.2 C16.2 C17.2 C23.2 C28.2 C30.2 C31.2 C32.2 C33.2 C34.2 C35.2 C36.2 C37.2 C38.2 DBG1.1 IC1.6 IC1.17 IC1.30 IC1.32 IC1.33 IC1.39 IC1.52 IC1.62 IC1.72 IC1.84 IC1.95 IC1.108 IC1.121 IC1.131 IC1.144 IC2.6 IC2.16 IC2.25 IC2.30 IC2.31 R5.2 R6.2 R17.1 U4.2 U4.4 | length 3590.8
  Layer 1 w10: C28.2 280.98,1195 285.83,1190.16 285.83,1189.17 295,1180 320,1180 323.91,1183.91 330.52,1183.91 346.81,1200.2 357.64,1200.2 IC2.16 ; C17.2 407.72,1434.17 420,1421.89 420,1416.31 425.47,1410.84 IC2.6 ; IC2.25 562.28,1201.1 623.39,1140 C14.2 ; IC2.30 552.36,1300.43 580.43,1300.43 640,1360 C16.2 ; IC2.31 552.36,1320.12 569.46,1320.12 608.67,1359.33 608.67,1363.67 645,1400 C15.2 ; C10.2 1513.19,1738.54 1524.02,1727.72 C9.2 1642.46,1727.72 1644.11,1726.06 IC1.6 ; C8.2 1496.97,1015 1514.68,1032.72 C7.2 ; C38.2 1495.83,1162.72 C37.2 ; C31.2 1641.87,1507.28 1644.11,1509.53 IC1.17 ; C36.2 1548.19,1270 1555.58,1262.61 v1@1566.95,1262.61 ; v1(1566.95,1273.05) v1@1566.95,1262.61 ; C37.2@1570.98,1162.72 1592.39,1184.13 1592.39,1192.39 v1@1595,1195 ; C7.2@1575.98,1032.72 1608.88,1065.62 1608.88,1112.98 ; v1(1596.35,1112.98) 1608.88,1112.98 ; v1(1601.08,1188.92) v1@1595,1195 ; IC1.33 1666.34,1193.66 1636.94,1193.66 1608.88,1165.6 1608.88,1112.98 ; IC1.32 1614.25,1214.25 v1@1595,1195 ; IC1.30 1590.06,1253.62 1583.69,1260 1569.56,1260 v1@1566.95,1262.61 ; C33.2 1745.26,2034.74 1745.26,1903.01 IC1.144 ; IC1.39 1783.98,1056.34 1783.98,1021.03 1783.19,1020.25 1783.19,996.81 1788.19,991.81 1788.19,966.81 1790.22,964.78 1790.22,930.22 C4.2 ; R17.1 1993.48,410.22 2006.63,423.36 2021.92,423.36 v1(2024.53,425.96) ; C34.2 1997.28,1977.1 2001.42,1972.96 IC1.131 ; IC1.52 2041.69,1056.34 2041.69,933.74 C5.2 ; C35.2 2165,2002.72 2165,1975 2198.27,1941.73 IC1.121 ; IC1.62 2237.64,988.65 2245,981.29 C3.2 2245,929.02 2252.56,921.46 C2.2 ; IC1.72 2434.49,1034.11 2455,1013.6 C6.2 ; IC1.84 2568.36,1352.05 2576.31,1360 C30.2 ; IC1.95 2575.64,1568.58 2579.29,1572.24 v1(2582.98,1572.24) ; IC1.108 2535.89,1824.49 2554.11,1842.72 C32.2
  Layer 1 w20: v1(1402.5,2825) 1403.19,2825.69 1403.19,2840.24 1427.28,2864.33 R5.2 ; R6.2 1705.59,2864.84 1705.59,2841.57 1721.18,2825.98 v1(1721.18,2825) ; C23.2 v1(2382.5,2775) U4.2 ; v1(3147.98,1692.24) 3148.67,1691.55 3148.67,1674.44 3165,1658.11 DBG1.1
  Layer 2 w20: v1(1402.5,2825) 1605.15,2825 1617.5,2812.65
  other v1: 1790,965 2042.98,972.24 2247.98,977.24 2452.98,987.24 585,1175 321.3,1181.3 615,1335 2580,1360 621.83,1376.83 420,1420 1555,1505 1575,1725 2592.06,1842.72 1995,1990 2166.3,1991.28 1745,2005 2886.33,2628.27 2814.71,2633.96 2975.83,2643.19 2809.27,2678.94 3015.13,2711.66 2906.87,2743.19 2811.38,2782.39 3008.33,2850.69 2855.83,2860.69 2935.95,2874.23 3005.83,2928.19 2813.33,2940.69
5V: C22.2 C47.2 J4.02 J5.1@322.91,2735 J5.2@630,2457.5 R16.1 U4.3 | length 7002.7
  Layer 1 w20: v1(712.5,390) 713.48,390 716.2,392.72 R16.1 ; v2(2345,2655) 2353.12,2655 2373.12,2675 U4.3@2453.74,2675 ; C22.2 2400.67,2617.93 2445.04,2662.3 2445.04,2666.3 U4.3@2453.74,2675 ; U4.3 U4.3@2453.74,2675
  Layer 1 w50: C47.2 493.62,2856.75 491.99,2855.12 491.99,2819.49 421.39,2748.89 336.8,2748.89 322.91,2735 459.61,2598.31 494.19,2598.31 624.09,2468.41 624.09,2466.6 627.74,2462.96 J5.2@629.03,2462.96 ; J4.02 2317.5,2682.5 v2(2345,2655)
  Layer 2 w20: J5.1@322.91,2745 322.91,2502.85 185,2364.93 185,930 711.81,403.19 711.81,390.69 v1(712.5,390)
  Layer 2 w50: J5.1@322.91,2745 2255,2745 v2(2345,2655)
CLK: IC1.41 IC2.14 | length 1976
  Layer 1 w10: v1(350,940) 350,1040 259.17,1130.83 259.17,1207.54 292.1,1240.47 IC2.14 ; IC1.41 1825.16,1056.34 1825.16,1006.22 v1(1826.38,1005)
  Layer 2 w20: v1(350,940) 963.6,940 965.26,938.34 1688.34,938.34 1755,1005 v1(1826.38,1005)
DATA0: IC1.37 IC2.24 | length 1553.2
  Layer 1 w10: IC2.24 523.9,1126.1 540,1110 ; 1710,935 1710,998.6 1745.51,1034.11 IC1.37
  Layer 1 w20: 540,1110 840,810 1585,810 1710,935
DATA1: IC1.46 IC2.23 | length 1804.8
  Layer 1 w10: IC2.23 504.21,1110.79 515,1100 ; 1919.82,925.18 1922.68,928.03 IC1.46
  Layer 1 w20: 515,1100 515,1099.64 829.64,785 1775,785 1915.18,925.18 1919.82,925.18
DATA2: IC1.47 IC2.22 | length 1883.3
  Layer 1 w10: IC2.22 484.53,1095.47 490,1090 ; 1942.36,912.36 IC1.47
  Layer 1 w20: 490,1090 490,1089.29 819.29,760 1790,760 1942.36,912.36
DATA3: IC1.69 IC2.21 | length 2359.9
  Layer 1 w10: IC2.21 464.84,1079.09 471.97,1071.97 ; 2369.79,917.02 2375.43,922.65 IC1.69
  Layer 1 w20: 471.97,1071.97 808.93,735 2187.78,735 2369.79,917.02
DATA4: IC1.70 IC2.20 | length 2451.5
  Layer 1 w10: IC2.20 445.16,1059.84 460,1045 ; 2310,810 2310,828.94 2395.12,914.06 IC1.70
  Layer 1 w20: 460,1045 800,705 2205,705 2310,810
DATA5: IC1.73 IC2.19 | length 2887.7
  Layer 1 w10: IC2.19 425.47,1024.53 440,1010 ; IC1.73 2535.89,1135.51 2536.79,1134.61 2536.79,1134.14 2555,1115.93
  Layer 1 w20: 440,1010 775,675 2455.59,675 2592.5,811.91 2592.5,1078.43 2555,1115.93
DATA6: IC1.74 IC2.18 | length 3027.7
  Layer 1 w10: IC2.18 405.79,999.21 420,985 ; IC1.74 2513.66,1154.29 2552.34,1154.29 2630,1076.63 2630,1037.95
  Layer 1 w20: 420,985 760,645 2460.95,645 2630,814.05 2630,1037.95
DATA7: IC1.135 IC2.17 | length 2086.5
  Layer 1 w10: v1(370,1090) 370,1093.69 386.1,1109.79 IC2.17 ; IC1.135 1923.58,1903.66 1923.58,1946.77 1925,1948.19 v1(1925,1975)
  Layer 2 w20: v1(370,1090) 551.38,1090 1438.19,1976.81 1882.21,1976.81 1883.33,1975.69 1924.31,1975.69 v1(1925,1975)
Debug: IC1.66 R18.1 | length 682.8
  Layer 1 w10: v1(2272.5,447.5) 2275.11,444.89 2275.11,439.13 2306.52,407.72 R18.1 ; v1(2316.38,1000) IC1.66
  Layer 2 w10: v1(2272.5,447.5) 2272.5,956.12 v1(2316.38,1000)
DIR: IC1.28 IC2.12 | length 1896.3
  Layer 1 w10: v1(295,1020) 229.17,1085.83 229.17,1219.97 289.05,1279.84 IC2.12 ; v1(1556.53,1328.66) 1585.81,1328.66 1621.48,1292.99 IC1.28
  Layer 2 w20: v1(295,1020) 1220,1020 1527.97,1327.97 1555.83,1327.97 v1(1556.53,1328.66)
GND: C1.1 C2.1 C3.1 C4.1 C5.1 C6.1 C7.1 C8.1 C9.1 C10.1 C12.1 C13.1 C14.1 C15.1 C16.1 C17.1 C22.1 C23.1 C28.1 C29.1 C30.1 C31.1 C32.1 C33.1 C34.1 C35.1 C36.1 C37.1 C38.1 C39.2 C40.2 C41.1 C42.1 C43.1 C44.1 C45.2 C46.2 C47.1 D1.1 D2.2 D3.2 D4.2 D5.1 D?.1 DBG1.3 DBG1.5 GND.PAD IC1.16 IC1.31 IC1.38 IC1.51 IC1.61 IC1.83 IC1.94 IC1.107 IC1.120 IC1.130 IC1.138 IC2.1 IC2.2 IC2.9 IC2.33 J1.1 J1.2 J1.3 J1.4 J1.A1-B12 J1.B1-A12 J4.01 J4.03 J4.07 J4.08 J5.2@130,2735 J5.3 R1.2 R2.2 R12.1 U4.1 X1.2 X1.4 | length 4052.8
  Layer 1 w10: C28.1 280.98,1159.57 297.94,1142.61 307.39,1142.61 v1(310,1140) ; v1@355,1490 355,1478.27 372.28,1460.98 C17.1 ; IC2.9 386.1,1338.9 IC2.33@417.5,1307.5 ; v1@390,1625 391.46,1626.46 C29.1 ; v1(455,1270) 504.21,1319.21 IC2.2 IC2.1 ; v1@745,2345 748.78,2341.22 748.78,2315.75 R1.2 ; R2.2 764.53,1941.06 775.28,1930.31 779.21,1930.31 784.53,1925 v1@810,1925 ; D1.1 777.83,2183.19 798.19,2183.19 v1(805,2190) ; v1(890,1170) 890,1181.69 X1.4@922.76,1214.45 ; X1.4 X1.4@922.76,1214.45 ; C39.2 955.1,1182.11 X1.4@922.76,1214.45 ; C40.2 984.9,1427.89 X1.2@1017.24,1395.55 ; X1.2 X1.2@1017.24,1395.55 ; v1@1055,1445 1055,1433.31 X1.2@1017.24,1395.55 ; v1(1152.5,1926.24) 1206.5,1926.24 C44.1 ; v1(1172.5,1857.5) 1172.5,1853.81 1187.24,1839.07 1193.25,1839.07 1219.83,1812.5 C45.2 ; C46.2 1248.25,1400 1281.39,1366.86 1290.39,1366.86 v1(1292.99,1364.25) ; GND.PAD 1310.09,2542.41 1310.09,2501.31 v1(1338.49,2472.92) ; C43.1 1430.71,1927.5 v1(1465,1927.5) ; C10.1 1513.19,1681.46 1524.02,1692.28 C9.1 ; C8.1 1534.65,957.91 1554.33,977.6 ; C38.1 1509.69,1121.14 1534.84,1121.14 1540.98,1127.28 C37.1 ; C1.1 1504.65,1380.35 v1(1504.65,1400) ; C31.1 1506.14,1543.86 1563.86,1543.86 v1(1565,1545) 1568.69,1545 1584.47,1529.21 IC1.16 ; C36.1 1517.28,1232.28 v1@1534.45,1232.28 ; v1(1534.45,1240.55) v1@1534.45,1232.28 ; v1(1566.78,965.15) 1554.33,977.6 ; C7.1 1574.02,997.28 1554.33,977.6 ; IC1.31 1552.62,1233.94 1548.69,1230 1536.73,1230 v1@1534.45,1232.28 ; v1(1675,2025) 1677.24,2027.24 1701.81,2027.24 1703.74,2029.17 1704.72,2029.17 1709.57,2034.02 C33.1 ; C4.1 v1(1755,960) 1757.61,962.61 1757.61,984.22 1765.2,991.81 IC1.38 ; IC1.138 1864.31,1903.44 1864.31,1949.31 v1(1865,1950) ; D5.1 1996.97,153.13 v1(2047.5,153.13) ; C5.1 v1(2010,979.42) 2021.1,990.52 IC1.51 ; IC1.130 2021.1,1967.42 2035,1981.31 v1(2035,1985) 2033.86,1986.14 2033.86,2028.86 C34.1 ; C2.1 2197.44,916.89 2209.57,929.02 C3.1 2209.57,980.78 2217.95,989.16 IC1.61 ; IC1.120 2217.95,1969.27 2230,1981.31 v1(2230,1985) 2228.86,1986.14 2228.86,2028.86 C35.1 ; D?.1 2358.84,153.66 v1(2380,132.5) ; v1(2353.12,2565.35) 2356.74,2565.35 2373.89,2582.5 C22.1 ; C23.1 2433.96,2855.22 2453.74,2875 U4.1 ; C6.1 2495.28,934.84 2495.28,946.59 2505,956.31 v1(2505,960) ; IC1.83 2563.95,1332.36 2571.31,1325 v1(2575,1325) 2575.22,1324.78 2624.78,1324.78 C30.1 ; IC1.94 2557.42,1548.9 2566.31,1540 v1(2570,1540) ; IC1.107 2512.85,1804.9 2569.9,1804.9 2571.14,1806.14 2628.86,1806.14 C32.1 ; C41.1 2519.95,882.45 v1(2540,902.5) ; v1(2637.87,1889) C42.1 ; v1(2915,1730) 2915,1727.6 2932.76,1709.84 2932.76,1706.29 2944.69,1694.36 2944.69,1678.17 2965,1657.85 DBG1.5 ; DBG1.3 3069.11,1659.11 3069.11,1685.43 3080,1696.31 v1(3080,1700)
  Layer 1 w12: C14.1 695.43,1140.98 712.78,1158.33 712.78,1162.78 v1(715,1165) 712.78,1167.22 712.78,1189.78 C13.1 ; R12.1 701.36,1458.64 701.36,1361.36 C16.1 705.14,1357.58 705.14,1307.42 C12.1
  Layer 1 w20: J1.2 272.06,1948.7 281,1957.65 281,1990.98 282.82,1992.8 J1.B1-A12 ; J1.1 272.06,2288.86 281,2279.91 281,2246.57 282.82,2244.76 J1.A1-B12
  Layer 1 w25: C47.1 504.63,2955.37 607.87,2955.37 v2(610,2957.5)
  other v1: 2195,895 1536.34,1122.64 420,1310 490,1310 700,1430 1055,1439.15 353.62,1492.61 390.02,1624.83 1496.34,1681.46 2570,1805 807.53,1925.05 745.63,2344.37
  other v2: 3155.12,183.53 2811.28,199.6 3444.34,222.09 169.76,405.27 362.57,636.64 146.92,835.01 3103.71,1144.38 2923.75,1240.78 3704.64,1260.06 3334.42,1267.51 3364.42,1605.88 3654.42,1607.51 3231.92,1950.01 3602.49,1989.25 2881.92,2090.01 2911.92,2342.51 3311.92,2362.51 3610.44,2365.24 3170,2490 3394.42,2560.01 3436.92,2935.01 3146.92,2950.01 711.92,3170.01 369.42,3182.51 3134.42,3202.51 1079.42,3207.51 3395.96,3209.91 2874.42,3225.01 366.92,3525.01 734.42,3542.51 3109.99,3543.54 1081.92,3557.51 2871.92,3560.01 3426.92,3600.01
  other v3: 200.77,168.45 3748.27,168.45 200.77,3773.45 3748.27,3773.45
HSE_IN: C45.1 IC1.23 Y2.1 | length 693.6
  Layer 1 w10: Y2.1 1243.78,1687.15 1494.11,1436.81 1546.42,1436.81 1591.81,1391.42 IC1.23
  Layer 1 w20: Y2.1 1230,1754.55 1250.33,1774.88 1250.33,1812.36 C45.1
HSE_OUT: C46.1 IC1.24 Y2.2 | length 620.8
  Layer 1 w10: Y2.2 1391.86,1517.85 1487.9,1421.81 1540.2,1421.81 1585.6,1376.42 1604.8,1376.42 1609.48,1371.73 IC1.24
  Layer 1 w20: C46.1 1217.6,1505.45 Y2.2
I2C_SCL: IC1.139 J4.09 R6.1 | length 2169.9
  Layer 1 w10: IC1.139 1843.94,1811.06 v1(1845,1810)
  Layer 1 w20: v1(1617.5,2865) R6.1
  Layer 3 w20: J4.09 v1(1617.5,2865) 1617.5,2040.42 1831.81,1826.11 1831.81,1824.17 1845,1810.98 v1(1845,1810)
I2C_SDA: IC1.140 J4.10 R5.1 | length 2194.6
  Layer 1 w10: v1(1790.69,1815) 1810.34,1834.65 1810.34,1840.34 1824.25,1854.25 IC1.140
  Layer 1 w20: R5.1 v1(1517.5,2865)
  Layer 3 w20: J4.10 v1(1517.5,2865) 1517.5,2088.19 v1(1790.69,1815)
LSE_IN: C43.2 IC1.8 Y1.1 | length 534
  Layer 1 w10: v1(1407.5,1877.5) 1406.79,1877.5 1349.59,1934.7 Y1.1 1349.59,1960.3 1363.58,1974.29 C43.2 ; v1(1597.5,1691.3) 1602.11,1686.69 IC1.8
  Layer 2 w10: v1(1407.5,1877.5) 1488.04,1796.96 1488.04,1781.12 1575.25,1693.91 1594.89,1693.91 v1(1597.5,1691.3)
LSE_OUT: C44.2 IC1.9 Y1.2 | length 608.2
  Layer 1 w10: C44.2 1208.86,1966.4 1218.43,1956.83 1245.92,1956.83 1255.25,1947.5 Y1.2 1292.5,1904.86 v1(1385,1812.36) ; v1(1575,1667.01) IC1.9
  Layer 2 w10: v1(1385,1812.36) 1429.65,1812.36 v1(1575,1667.01)
Micro_DM: IC1.103 J3.1 | length 1776.4
  Layer 1 w10: v1(2390,1720) 2393.69,1720 2399.75,1726.06 IC1.103
  Layer 1 w20: J3.1 1170,2190 2155,2190 v1(2200,2145)
  Layer 2 w20: v1(2200,2145) 2200,1850 2330,1720 v1(2390,1720)
Micro_DP: IC1.104 J2.1 | length 1810.6
  Layer 1 w10: v1(2390,1775) 2419.25,1745.75 IC1.104
  Layer 1 w20: J2.1 2155,2300 v1(2320,2135)
  Layer 2 w20: v1(2320,2135) 2320,1805 2349.31,1775.69 2389.31,1775.69 v1(2390,1775)
NetD2_1: D2.1 R14.2 | length 181.4
  Layer 1 w20: D2.1 1682.5,340.45 1696.83,354.78 R14.2
NetD3_1: D3.1 R15.2 | length 186.6
  Layer 1 w20: D3.1 1360,322.95 1386.83,349.78 R15.2
NetD4_1: D4.1 R16.2 | length 184.7
  Layer 1 w20: D4.1 1005,352.95 1009.33,357.28 R16.2
NetD5_2: D5.2 R17.2 | length 142.4
  Layer 1 w20: R17.2 1993.17,374.78 1995,372.95 D5.2
NetD?_2: D?.2 R18.2 | length 135.9
  Layer 1 w10: D?.2 R18.2
NetIC2_4: IC2.4 R13.2 | length 193.2
  Layer 1 w10: IC2.4 464.92,1366.54 464.92,1559.49 R13.2
NetJ1_A5: J1.A5 R1.1 | length 464.9
  Layer 1 w10: J1.A5 335.89,2167.99 472.89,2305 R1.1
NetJ1_B5: J1.B5 R2.1 | length 456.6
  Layer 1 w10: J1.B5 544.45,2049.88 649.33,1945 R2.1
NRST: C1.2 DBG1.10 IC1.25 | length 1773.6
  Layer 1 w10: C1.2 1560.8,1380 1579.38,1361.42 1598.58,1361.42 1607.95,1352.05 IC1.25 1723.36,1352.05 1725.86,1354.54 1731.77,1348.63 1756.37,1348.63 v1(1758.58,1346.42) ; v1(2610,1450) 3045,1450 3165,1570 DBG1.10
  Layer 2 w10: v1(1758.58,1346.42) 1759.34,1346.42 1777.92,1365 2525,1365 v1(2610,1450)
NXT: IC1.29 IC2.11 | length 1977.4
  Layer 1 w10: v1(295,975) 214.17,1055.83 214.17,1226.18 287.52,1299.53 IC2.11 ; v1(1557.47,1300.05) 1557.52,1300 1584.28,1300 1589.28,1295 1598.26,1295 1619.95,1273.31 IC1.29
  Layer 2 w20: v1(295,975) 1230.99,975 1555.35,1299.36 1556.77,1299.36 v1(1557.47,1300.05)
OSCOPE_IN: IC1.55 R14.1 | length 859.5
  Layer 1 w10: IC1.55 2099.84,1008.34 v1(2119.53,988.65)
  Layer 1 w20: R14.1@1698.33,390.37 1717.26,409.31 1734.31,409.31 v1(1735,410)
  Layer 2 w10: v1(1735,410) 2119.53,794.53 v1(2119.53,988.65)
PWR_IN: IC1.54 R15.1 | length 1017.1
  Layer 1 w10: v1(2080.16,990.52) IC1.54
  Layer 1 w20: R15.1 1388.17,385.22 1403.22,400.27 1424.31,400.27 v1(1425,400.96)
  Layer 2 w10: v1(1425,400.96) 1502.55,400.96 2077.55,975.97 2077.55,987.92 v1(2080.16,990.52)
RBIAS: IC2.32 R12.2 | length 174.3
  Layer 1 w10: IC2.32 562.28,1338.9 563.19,1339.8 563.19,1357.64 664.57,1459.02 R12.2
SPI_MISO: IC1.42 J4.05 | length 2754.6
  Layer 1 w10: IC1.42 v1(1843.94,1122.5)
  Layer 4 w20: v1(1843.94,1122.5) 1843.94,1771.02 1951.81,1878.89 1951.81,1984.73 2017.5,2050.42 J4.05
SPI_MOSI: IC1.43 J4.04 | length 2787.9
  Layer 1 w10: IC1.43 1863.62,1102.81 v1(1883.31,1122.5)
  Layer 4 w20: v1(1883.31,1122.5) 1883.31,1650.37 2092.5,1859.57 2092.5,3462.5 2117.5,3487.5 J4.04
SPI_NSS: IC1.40 IC1.44 | length 219.1
  Layer 1 w10: IC1.40 1804.57,995.97 1821.11,979.42 1873.78,979.42 1883.31,988.94 IC1.44
SPI_SCK: IC1.126 J4.06 | length 1991.9
  Layer 1 w10: v1(1925,2082.5) 2060,2082.5 2099.84,2042.66 IC1.126
  Layer 4 w20: J4.06 1917.5,2090.98 1925,2083.48 v1(1925,2082.5)
STP: IC1.26 IC2.13 | length 1815.4
  Layer 1 w10: v1(295,1060) 244.17,1110.83 244.17,1213.76 290.57,1260.16 IC2.13 ; v1(1486.81,1345) 1535.12,1345 1540.59,1350.47 1569.12,1350.47 1573.17,1346.42 1589.27,1346.42 1603.32,1332.36 IC1.26
  Layer 2 w20: v1(295,1060) 1200,1060 1336.25,1196.25 1336.25,1208.06 1443.36,1315.18 1456.99,1315.18 v1(1486.81,1345)
SWCLK: DBG1.4 IC1.109 | length 882.1
  Layer 1 w10: IC1.109 2434.61,1902.88 2434.61,1938.79 2440.47,1944.65 2939.43,1944.65 2944.78,1939.3 3040.68,1756.61 cw(c2990,1730) 3041.12,1755.75 3060,1718.28 3060,1710 3057.07,1707.07 3037.33,1687.33 3037.33,1677.33 DBG1.4
SWDIO: DBG1.2 IC1.105 | length 798.7
  Layer 1 w10: IC1.105 2535.89,1765.43 2539.67,1761.65 2545.93,1761.65 2551.79,1755.8 2551.79,1735.7 2551.79,1726.4 2565.69,1712.5 2757.5,1712.5 v1(2840,1795) ; v1(3080,1780) 3115,1745 DBG1.2
  Layer 2 w10: v1(2840,1795) 2855,1810 3050,1810 v1(3080,1780)
SWO: DBG1.6 IC1.133 | length 1247.6
  Layer 1 w10: IC1.133 1962.05,1841.64 1975,1828.69 v1(1975,1825) ; v1(2605,1515) 2890,1515 2944.69,1569.69 2944.69,1581.83 2965,1602.15 DBG1.6
  Layer 2 w10: v1(1975,1825) 2285,1515 v1(2605,1515)
USB_DM: D1.3 IC2.8 J1.A7 J1.B7 J3.2 | length 1876.5
  Layer 1 w10: 180,1583.39 386.1,1377.28 IC2.8 ; J1.B7 291.42,2149.21 256.63,2149.21 254.03,2151.81 201.81,2151.81 195,2145 195,2115 203.19,2106.81 238.33,2106.81 239.7,2108.19 291.57,2108.19 J1.A7 676.85,2108.94 697.2,2088.58 D1.3
  Layer 1 w20: 180,1583.39 180,1856.22 ; 180,1860 180,2130 195,2145 ; D1.3 742.48,2125 993.69,2125 1013.69,2145 J3.2
USB_DP: D1.2 IC2.7 J1.A6 J1.B6 J2.2 | length 1826.1
  Layer 1 w10: v1(230,2085) 233.69,2085 237.94,2089.25 J1.B6 ; v1(245,2130) 245.69,2129.31 291.63,2129.31 J1.A6 575.28,2128.62 616.93,2170.28 D1.2 ; 320,1475 320,1469.34 404.88,1384.46 404.88,1367.36 IC2.7
  Layer 1 w20: v1(230,2085) 205,2060 205,1590 320,1475 ; D1.2 697.2,2177.24 819.96,2300 J2.2
  Layer 2 w10: v1(230,2085) 226.31,2085 215.46,2095.86 210.86,2095.86 205,2101.72 205,2120 215,2130 v1(245,2130)
VBUS: C29.2 D1.4 J1.A4-B9 J1.B4-A9 J5.1@730,2457.5 R13.1 VBUS.PAD | length 510.1
  Layer 1 w10: J1.B4-A9 299.13,2017.48 323.83,2017.48 336.31,2005 v1(340,2005) ; J1.A4-B9 296.45,2217.39 332.39,2217.39 v1(335,2220) ; R13.1 464.02,1595 448.54,1610.47 C29.2 482.85,1670 492.85,1680 v1(495,1680) ; v1(775,2040) 773.9,2041.1 773.9,2078.62 D1.4 772.8,2070.87 781.85,2061.81 784.03,2061.81 900.43,1945.41 900.43,1912.07 VBUS.PAD
VCAP1: C41.2 IC1.71 | length 226.3
  Layer 1 w10: C41.2 2401.95,899.67 2414.8,912.53 IC1.71
VCAP2: C42.2 IC1.106 | length 203.1
  Layer 1 w10: IC1.106 2559.04,1785.12 2573.15,1771 C42.2
VDD1.8: C13.2 IC2.15 IC2.26 | length 439.7
  Layer 1 w10: v1(320,1218.66) 343.78,1218.66 345,1219.88 357.64,1219.88 IC2.15 ; IC2.26 599.21,1220.79 625,1195 C13.2
  Layer 2 w20: v1(320,1218.66) 595.36,1218.66 604.02,1210 v1(605,1210)
VDDA1.8: 1V8.PAD C12.2 IC2.29 | length 493.5
  Layer 1 w10: IC2.29 590.78,1279.84 v1(603.36,1292.42) 615.94,1305 C12.2 652.44,1303.04 674.1,1281.38 680,1281.38 681.34,1280.04 722.8,1280.04 766.62,1323.86 766.62,1486.62 1V8.PAD
XI: C40.1 IC2.28 R11.2 X1.3 | length 747.5
  Layer 1 w10: IC2.28 810.98,1260.16 X1.3@922.76,1371.93 ; C40.1 955.1,1427.89 922.76,1395.55 X1.3 X1.3@922.76,1371.93 ; R11.2 961.97,1332.72 X1.3@922.76,1371.93
XO: C39.1 IC2.27 R11.1 X1.1 | length 758.3
  Layer 1 w10: IC2.27 812.51,1240.47 852.04,1280 975.31,1280 X1.1@1017.24,1238.07 ; C39.1 984.9,1182.11 1017.24,1214.45 X1.1 X1.1@1017.24,1238.07 ; R11.1 1094.02,1297.28 1053.43,1256.69 1035.87,1256.69 X1.1@1017.24,1238.07
pads on no net: DBG1.7 DBG1.8 DBG1.9 DBG1.A DBG1.B DBG1.C DBG1.D DBG1.E DBG1.F DBG1.G IC1.1 IC1.2 IC1.3 IC1.4 IC1.5 IC1.7 IC1.10 IC1.11 IC1.12 IC1.13 IC1.14 IC1.15 IC1.18 IC1.19 IC1.20 IC1.21 IC1.22 IC1.27 IC1.34 IC1.35 IC1.36 IC1.45 IC1.48 IC1.49 IC1.50 IC1.53 IC1.56 IC1.57 IC1.58 IC1.59 IC1.60 IC1.63 IC1.64 IC1.65 IC1.67 IC1.68 IC1.75 IC1.76 IC1.77 IC1.78 IC1.79 IC1.80 IC1.81 IC1.82 IC1.85 IC1.86 IC1.87 IC1.88 IC1.89 IC1.90 IC1.91 IC1.92 IC1.93 IC1.96 IC1.97 IC1.98 IC1.99 IC1.100 IC1.101 IC1.102 IC1.110 IC1.111 IC1.112 IC1.113 IC1.114 IC1.115 IC1.116 IC1.117 IC1.118 IC1.119 IC1.122 IC1.123 IC1.124 IC1.125 IC1.127 IC1.128 IC1.129 IC1.132 IC1.134 IC1.136 IC1.137 IC1.141 IC1.142 IC1.143 IC2.3 IC2.5 IC2.10 J1. J1.A8 J1.B8

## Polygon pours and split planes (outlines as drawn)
3V3 on Layer 2 "3V3_L02_P001" (solid, pour order 1): 1555,3607.5 1555,2420 565,1430 60,1430 60,105 55,100 3867.5,100 3867.5,3607.5
VBUS on Layer 2 "VBUS_L02_P000" (solid, pour order 0): 60,2515 60,1625 555,1625 1445,2515
GND on Layer 4 "GND_L04_P002" (solid, pour order 2): 55,3885 55,45 3875,45 3875,3885
GND on Layer 3 "GND_L03_P003" (solid, pour order 3): 55,3883.77 55,52.5 3867.5,52.5 3867.5,3886.73
GND on Layer 1 "GND_L01_P004" (solid, pour order 4): 55,3883.77 55,52.5 3867.5,52.5 3875,45 3883.94,53.94 3883.94,3886.73

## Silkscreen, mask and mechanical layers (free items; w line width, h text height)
Top Overlay:
  drawing of 5 lines, arcs and shapes, not listed
  text "3V3 LDO" at 2475,3072.5 h60
  text "UNPLUG 5V BEFORE JUMP" at 425.43,2634.76 h60
  text "USB" at 717.5,2535 h60
  text "5V" at 557.5,2532.5 h60
  text "DP" at 970,2442.5 h60
  text "USB" at 115.12,2402.5 h60
  text "DM" at 978.5,1977.5 h60
  text "USB HS" at 450,950 h60
  text "Oscope_In" at 1627.5,519.99 h60
  text "5V" at 975,515 h60
  text "EECS473 Group 14 F25" at 2559.36,514.99 h60
  text "PD_In" at 1267.5,510 h60
  text "Main Board Rev2" at 2879.36,420 h60
  text "3V3" at 2071.75,172.65 h60
  text "STM" at 2369.25,172.65 h60
Bottom Overlay:
  text "I am ... cogito ergo sum ... I think, therefore I am." at 2285,2947.5 h60
Mechanical 1:
  circle w10: c3748.27,3773.45 r70.87
  circle w10: c3748.27,168.45 r70.87
  circle w10: c200.77,168.45 r70.87
  circle w10: c200.77,3773.45 r70.87
  lines w10: 0,2845 0,2890 ; 0,63.28 ccw(c68.28,63.28) 20,15 ccw(c56.21,51.21) 56.21,0 62.07,0 3867.5,0 ccw(c3867.5,66.39) 3914.45,19.45 3915,20 ccw(c3861.87,73.13) 3937.01,73.13 3937.01,80 3937.5,80 cw(c3938.69,81.19) 3937.01,81.19 3937.01,3886.73 3937.01,3891.01 ccw(c3896.01,3891.01) 3925,3920 ccw(c3883.94,3878.94) 3883.94,3937.01 3875,3937.01 97.5,3937.01 82.7,3937.01 ccw(c82.7,3844.8) 17.5,3910 ccw(c59.75,3867.75) 0,3867.75 0,3862.5 0,75 0,63.28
